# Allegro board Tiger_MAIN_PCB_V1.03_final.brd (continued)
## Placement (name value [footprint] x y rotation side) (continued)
R133  0  [RC0603N]  181.15 43.72 270 bottom
R134  20K  [RC0402N]  181.42 68.94 0 top
R136  33  [RC0402N]  178.14 37.99 90 top
R137  33  [RC0402N]  177.82 51.6 270 top
R138  33  [RC0402N]  176.02 37.98 90 top
R139  33  [RC0402N]  179.06 51.63 270 top
R140  2.2K  [RC0402N]  183.99 74.2 90 top
R142  0  [RC0402N]  172.97 54.66 0 bottom
R152  100k  [RC0402N]  238.32 43.35 270 bottom
R155  0  [RC0402N]  134.45 25.91 270 bottom
R168  0  [RC0402N]  229.78 96.46 0 bottom
R174  0  [RC0402N]  89.52 35.13 0 top
R175  0  [RC0402N]  76.05 56.64 270 top
R180  10K  [RC0402N]  80.56 56.19 0 top
R181  0  [RC0402N]  82.38 56.19 180 top
R182  1k  [RC0402N]  86.97 79.54 180 bottom
R183  0  [RC0402N]  160.35 92.37 0 top
R184  3.65K  [RC0402N]  229.01 98.95 180 bottom
R185  499  [RC0603N]  245.12 88.43 180 bottom
R187  0  [RC0402N]  89.49 40.08 180 top
R194  0  [RC0402N]  89.5 39.24 180 top
R196  100k  [RC0402N]  127.5 27.61 180 bottom
R197  0  [RC0402N]  88.96 44.49 270 top
R198  0  [RC0402N]  89.75 44.49 270 top
R199  10K  [RC0402N]  89.52 34.28 180 top
R200  0  [RC0402N]  78.07 56.19 0 top
R204  11K  [RC0402N]  229.78 97.24 0 bottom
R205  1.1k  [RC0402N]  229.78 98.06 180 bottom
R206  10K_NTC  [RC0402N]  231.61 98.06 180 bottom
R207  10K  [RC0402N]  233.15 93.7 0 bottom
R208  2k  [RC0402N]  235.46 83.25 180 top
R209  499  [RC0603N]  237.17 82.66 270 top
R210  1k  [RC0402N]  235.46 84.07 180 top
R211  3.01K  [RC0603N]  232.13 90.13 180 bottom
R212  365  [RC0402N]  233.15 92.75 0 bottom
R213  1.1k  [RC0402N]  242.98 101.36 180 bottom
R214  8.2K  [RC0402N]  242.98 100.41 0 bottom
R215  10K_NTC  [RC0402N]  244.29 100.88 90 bottom
R216  1k  [RC0402N]  242.35 94.65 270 bottom
R217  340  [RC0603N]  243.42 94.93 270 bottom
R218  0  [RC0402N]  231.77 83.43 90 bottom
R219  220K_NTC  [RC0603N]  231.24 87.34 270 bottom
R220  2.49k  [RC0402N]  237.39 96.34 270 bottom
R221  2k  [RC0402N]  245.2 81.64 0 bottom
R222  1.43K  [RC0603N]  238.42 99.13 270 bottom
R223  11K  [RC0402N]  245.51 84.06 90 bottom
R224  3.01K  [RC0603N]  243.4 91.66 270 bottom
R225  10K_NTC  [RC0402N]  245.01 80.41 0 bottom
R226  4.99K  [RC0402N]  240.24 98.66 270 bottom
R227  1k  [RC0402N]  239.46 98.66 270 bottom
R228  1k  [RC0402N]  243.73 81.19 90 bottom
R229  220K_NTC  [RC0603N]  236.36 98.64 270 bottom
R230  1.3K  [RC0402N]  245.51 95.96 270 bottom
R231  499  [RC0603N]  245.13 89.66 180 bottom
R232  12.1K  [RC0402N]  231.51 84.77 0 bottom
R233  100k  [RC0402N]  244.94 93.15 180 bottom
R234  88.7k  [RC0402N]  242.21 83.16 90 bottom
R235  64.9k  [RC0402N]  241.76 85.19 270 bottom
R236  0  [RC0402N]  44.22 57.03 180 bottom
R237  750  [RC0603N]  243.24 83.49 270 bottom
R238  0  [RC0402N]  230.96 83.43 90 bottom
R239  0  [RC0402N]  181.16 95.96 180 bottom
R240  0  [RC0402N]  89.52 36 0 top
R242  3.65K  [RC0402N]  242.98 102.2 0 bottom
R244  0  [RC0402N]  244.8 99.35 180 bottom
R246  0  [RC0805N]  123.74 80.68 180 bottom
R247  0  [RC0805N]  127.51 79.87 270 bottom
R249  0  [RC0402N]  211.74 96.83 0 bottom
R253  100k  [RC0402N]  183.73 51.09 90 top
R254  0  [RC0402N]  215.19 97.93 0 bottom
R255  0  [RC0402N]  181.47 60.26 0 top
R256  0  [RC0402N]  220.84 93.63 0 bottom
R258  0  [RC0402N]  162.33 89.4 90 bottom
R260  3.65K  [RC0402N]  245.2 82.45 0 bottom
R264  10K  [RC0402N]  179.63 60.26 180 top
R270  100K  [RC0402N]  175.67 29.56 180 bottom
R271  100K  [RC0402N]  175.76 28.62 0 bottom
R291  2.2  [RC0603N]  107.07 91.14 0 bottom
R303  2K  [RC1206N]  123.37 13.85 0 bottom
R306  0  [RC0402N]  112.55 46.72 90 bottom
R307  2.49k  [RC0603N]  120.62 34.37 90 bottom
R308  10k  [RC0402N]  132.91 41.55 180 bottom
R309  100k  [RC0402N]  115.81 44.28 0 bottom
R310  10k  [RC0402N]  132.91 42.69 180 bottom
R311  0  [RC0603N]  133.31 40 180 bottom
R312  0  [RC0603N]  133.32 38.79 0 bottom
R313  0  [RC0402N]  132.91 43.66 0 bottom
R315  1k  [RC0402N]  132.27 44.98 0 bottom
R316  15K  [RC0402N]  130.21 44.1 45 bottom
R317  0  [RC0603N]  132.57 46.23 0 bottom
R318  0  [RC0402N]  135.24 47.56 180 bottom
R319  0  [RC0603N]  101.6 31.91 0 top
R320  0  [RC0603N]  101.61 33.11 0 top
R321  10k  [RC0402N]  122.77 46.94 90 bottom
R322  0  [RC0603N]  101.47 34.95 0 top
R323  10k  [RC0402N]  123.58 46.94 90 bottom
R324  0  [RC0603N]  101.47 36.15 0 top
R325  1k  [RC0402N]  121.99 46.94 270 bottom
R326  1k  [RC0402N]  121.22 46.94 270 bottom
R327  0  [RC0603N]  104.62 37.84 0 bottom
R328  1k  [RC0402N]  127.65 35.48 90 bottom
R329  0  [RC0603N]  104.62 39.09 0 bottom
R330  0  [RC0603N]  104.59 40.83 0 bottom
R331  75  [RC0402N]  103.82 31.06 0 top
R332  75  [RC0402N]  103.74 34.03 0 top
R333  75  [RC0402N]  104.4 37.46 270 top
R334  75  [RC0402N]  104.4 39.49 90 top
R335  0  [RC0603N]  104.59 42.09 0 bottom
R336  0  [RC0603N]  9.59 89.64 90 top
R337  0  [RC0603N]  8.38 89.64 90 top
R338  0  [RC0603N]  5.26 89.92 90 top
R339  562  [RC0603N]  21.15 89.9 180 bottom
R340  0  [RC0603N]  6.47 89.92 90 top
R341  1k  [RC0402N]  22.99 90.18 270 bottom
R342  1k  [RC0402N]  25.27 88.5 180 bottom
R343  0  [RC0603N]  16.73 90.95 180 top
R344  0  [RC0603N]  16.73 92.15 180 top
R345  0  [RC0402N]  98.77 91 270 bottom
R346  1k  [RC0402N]  16.4 10.42 90 bottom
R347  0  [RC0603N]  35.06 20.09 180 bottom
R348  0  [RC0603N]  28.37 20.09 180 bottom
R349  75  [RC0402N]  8.88 19.5 0 bottom
R350  75  [RC0402N]  8.89 18.68 0 bottom
R355  4.7K  [RC0402N]  13.41 11.29 90 bottom
R356  4.7K  [RC0402N]  10.99 11.28 90 bottom
R357  20K  [RC0402N]  16.71 13.99 270 bottom
R358  39.2K  [RC0402N]  18.29 13.86 90 bottom
R359  20K  [RC0402N]  17.5 13.86 90 bottom
R360  0  [RC0603N]  20.9 15.87 0 bottom
R361  0  [RC0603N]  20.91 17.1 0 bottom
R362  33  [RC0402N]  19.62 18.18 0 bottom
R363  1k  [RC0402N]  23.68 25.09 180 top
R364  1k  [RC0402N]  25.23 27.18 90 top
R365  0  [RC0603N]  25.23 24.88 270 top
R366  0  [RC0603N]  26.22 27.65 270 top
R368  1.8K  [RC0603N]  192.67 12.77 0 bottom
R369  10k  [RC0402N]  19.22 29.05 0 bottom
R370  10k  [RC0402N]  20.66 26.25 90 bottom
R371  10k  [RC0402N]  24.09 29.87 270 bottom
R372  0  [RC0402N]  20.65 28.3 270 bottom
R373  1K  [RC0402N]  22.45 29.43 180 bottom
R377  0  [RC0402N]  136.94 38.75 0 bottom
R378  100k  [RC0402N]  135.38 34.66 90 bottom
R379  10K  [RC0402N]  44.19 69.43 0 bottom
R380  10K  [RC0402N]  44.19 70.71 0 bottom
R381  0  [RC0402N]  63.19 70.32 270 bottom
R382  10K  [RC0402N]  183.98 58.59 180 top
R383  0  [RC0805N]  36.8 56.84 90 bottom
R384  10K  [RC0402N]  55.14 74.22 270 bottom
R385  240  [RC0402L]  206.37 14.27 90 bottom
R386  10K  [RC0402N]  196.12 13.69 270 bottom
R387  10K  [RC0402N]  56.24 74.22 270 bottom
R388  10K  [RC0402N]  52.78 74.21 270 bottom
R389  10K  [RC0402N]  171.11 10.87 270 top
R390  0  [RC0402N]  64.52 69.86 180 bottom
R391  2.2  [RC0603N]  160.18 42.21 180 top
R392  220K  [RC0402N]  165.58 42.02 270 top
R393  10K  [RC0402N]  53.55 74.21 270 bottom
R395  0  [RC0402N]  44.53 64.85 180 bottom
R396  0  [RC0402N]  54.36 74.21 270 bottom
R397  0  [RC0402N]  57.04 74.21 270 bottom
R398  0  [RC0603N]  66.65 65.97 0 bottom
R399  10K  [RC0402N]  44.22 65.78 0 bottom
R400  10K  [RC0402N]  44.22 67.36 0 bottom
R401  100  [RC0402N]  63.62 62.02 0 bottom
R402  0  [RC0402N]  59.61 74.18 270 bottom
R403  0  [RC0402N]  70.27 61.98 180 bottom
R404  10K  [RC0402N]  44.22 66.56 0 bottom
R405  10K  [RC0402N]  44.22 58.74 0 bottom
R406  100k  [RC0402N]  42.93 58.27 90 bottom
R407  10K  [RC0402N]  42.3 61.9 90 bottom
R408  100k  [RC0402N]  61.44 63.94 270 top
R409  0  [RC0402N]  44.22 68.29 180 bottom
R410  0  [RC0402N]  63.58 61.25 180 bottom
R412  0  [RC0402N]  70.28 61.14 180 bottom
R413  100  [RC0402N]  58.33 74.21 90 bottom
R414  10K  [RC0402N]  63.59 60.47 0 bottom
R415  100k  [RC0402N]  65.73 58.12 0 bottom
R416  0  [RC0402N]  65.49 62.68 0 bottom
R417  0  [RC0402N]  51.22 74.26 90 bottom
R419  1k  [RC0402N]  44.22 57.88 180 bottom
R420  10K  [RC0402N]  46.3 74.25 270 bottom
R421  10K  [RC0402N]  47.15 74.25 90 bottom
R422  10K  [RC0402N]  50.45 74.25 270 bottom
R423  10K  [RC0402N]  49.62 74.25 90 bottom
R424  0  [RC0402N]  61.52 74.48 270 bottom
R425  10M  [RC0402N]  62.29 73.53 90 bottom
R426  100k  [RC0402N]  44.22 62.41 0 bottom
R427  4.7K  [RC0402N]  46.53 62.13 180 top
R428  4.7K  [RC0402N]  59.87 63.39 0 top
R429  0  [RC0402N]  128.75 82.38 180 bottom
R434  0  [RC0402N]  54.74 76.85 90 bottom
R435  10K  [RC0402N]  195.28 14.64 90 bottom
R436  10K  [RC0402N]  171.98 10.87 270 top
R437  0  [RC0402N]  55.57 76.85 90 bottom
R440  100k  [RC0402N]  130.39 85.71 270 bottom
R452  0  [RC0402N]  131.08 82.8 90 top
R453  0  [RC0402N]  130.26 81.73 270 top
R454  0  [RC0402N]  135.51 81.49 270 top
R455  10k  [RC0402N]  135.52 83.27 90 top
R456  10k  [RC0402N]  130.26 83.52 90 top
R457  0  [RC0402N]  70.29 60.31 0 bottom
R458  0  [RC0402N]  48.81 74.26 90 bottom
R462  0  [RC0402N]  47.99 74.26 90 bottom
R463  1M  [RC0402N]  27.39 62.4 180 bottom
R464  34K  [RC0402N]  185.55 29.26 0 bottom
R466  0  [RC0402N]  63.89 58.12 0 bottom
R468  0 ohm  [RC0805N]  170.97 24.34 180 bottom
R469  16k  [RC0603N]  185.57 28.21 180 bottom
R470  0  [RC0402N]  175.67 30.36 180 bottom
R471  240  [RC0402L]  215.15 21.79 90 bottom
R472  240  [RC0402L]  215.98 21.79 90 bottom
R476  0  [RC0402N]  194.43 12.48 90 bottom
R487  0  [RC0402N]  66.56 70.28 0 bottom
R488  0  [RC0402N]  64.59 63.95 180 bottom
R489  10K  [RC0402N]  169.44 10.87 270 top
R490  240  [RC0402L]  216.91 15.01 90 bottom
R491  10K  [RC0402N]  170.25 10.87 270 top
R492  240  [RC0402L]  216.81 21.78 270 bottom
R493  240  [RC0402L]  214.25 21.79 270 bottom
R494  240  [RC0402L]  213.35 21.79 270 bottom
R495  240  [RC0402L]  216.87 17.26 270 bottom
R496  240  [RC0402L]  217.85 21.77 270 bottom
R497  240  [RC0402L]  215.31 15.8 270 bottom
R498  470  [RC0402N]  213.85 14.28 270 bottom
R501  240  [RC0402L]  212.44 17.36 270 bottom
R502  0  [RC0402N]  213.84 16.08 270 bottom
R506  10K  [RC0402N]  56.86 75.97 180 bottom
R512  2  [RC0402N]  229.63 49.79 270 top
R513  25  [RC0402N]  228.07 49.79 270 top
R521  0  [RC0402N]  242.97 71.08 270 top
R522  0  [RC0402N]  243.92 71.08 270 top
R523  4.7K  [RC0402N]  245.61 76.19 90 top
R524  4.7K  [RC0402N]  245.61 74.35 90 top
R528  0  [RC0402N]  128.86 88.79 0 top
R534  16k  [RC0603N]  145.71 48.53 0 top
R535  100K  [RC0402N]  141.83 55.72 180 top
R536  18k  [RC0402N]  143.43 48.53 0 top
R537  100K  [RC0402N]  144.3 57.43 0 top
R541  0  [RC0402N]  129.42 82.4 90 top
R543  12k  [RC0603N]  242.35 37.71 0 bottom
R544  100k  [RC0402N]  241.93 41.56 90 bottom
R545  0  [RC0402N]  242.75 41.56 90 bottom
R546  12K  [RC0402N]  235.46 43.94 180 bottom
R547  20K  [RC0402N]  235.46 43.16 180 bottom
R548  0  [RC0402N]  239.11 41.54 90 bottom
R549  0  [RC0402N]  238.33 41.54 90 bottom
R550  0  [RC0402N]  236.76 41.53 90 bottom
R551  0  [RC0402N]  237.54 41.54 90 bottom
R552  0  [RC0402N]  239.88 41.55 270 bottom
R553  560K  [RC0603N]  240.88 42.01 270 bottom
R554  0  [RC0402N]  48.04 58.16 0 top
R555  100k  [RC0402N]  49.83 58.16 0 top
R557  1k  [RC0603N]  59.04 18.67 180 top
R558  1k  [RC0402N]  59.75 12.18 180 top
R559  1.8k  [RC0603N]  46.17 91.19 270 bottom
R560  1k  [RC0603N]  48.72 92.7 270 bottom
R561  1k  [RC0402N]  51.51 90.03 90 bottom
R562  1k  [RC0603N]  42.53 23.47 0 top
R563  1k  [RC0402N]  40.57 22.45 180 top
R564  0  [RC0603N]  46.95 21.16 0 top
R565  0  [RC0603N]  46.95 19.89 0 top
R567  0  [RC0603N]  62.54 21.2 0 top
R568  0  [RC0603N]  62.54 19.93 0 top
R569  30k  [RC0603N]  42.82 24.8 0 top
R570  30k  [RC0603N]  59.04 17.44 0 top
R590  10  [RC0603N]  239.22 82.57 180 top
R591  10  [RC0603N]  233.95 85.88 90 top
R606  0  [RC0402N]  128.45 83.96 0 top
R607  10K  [RC0402N]  160.22 18.71 270 top
R608  10K  [RC0402N]  161.88 13.56 0 top
R609  100  [RC0402N]  161.88 14.41 0 top
R611  100  [RC0402N]  100.78 11.32 0 top
R613  0 ohm  [RC0805N]  19.05 61.13 0 top
R616  0  [RC0402N]  181.33 51.09 270 top
R620  33  [RC0402N]  188.96 41.54 90 top
R621  33  [RC0402N]  196.23 48.9 90 top
R623  33  [RC0402N]  197.83 48.9 90 top
R624  0  [RC0402N]  192.7 44.4 315 top
R625  10k  [RC0402N]  191.29 41.61 270 top
R626  33  [RC0402N]  193.18 41.62 90 top
R627  0 ohm  [RC0603N]  244.57 20.51 90 top
R628  0 ohm  [RC0603N]  245.84 20.5 90 top
R629  0 ohm  [RC0603N]  7.89 12.75 180 top
R630  0 ohm  [RC0603N]  7.9 11.53 180 top
R632  150k  [RC0402N]  176.69 66.12 0 top
R633  1k  [RC0402N]  183.65 77.36 0 top
R636  18.7K  [RC0603N]  124.44 78.1 90 top
R638  12K  [RC0603N]  121.23 81.03 90 top
R645  430k  [RC0603N]  104.87 96.9 0 bottom
R648  430k  [RC0603N]  116.95 85.29 180 top
R660  0  [RC0402N]  166.28 55.3 90 top
R662  0  [RC0402N]  169.9 53.28 180 top
R663  100K  [RC0402N]  167.99 53.28 180 top
R667  0  [RC0402N]  235.46 80.92 180 top
R668  0  [RC0402N]  238.96 81.57 180 top
R669  88.7k  [RC0402N]  232.82 86.55 180 bottom
R671  7.5K  [RC0402N]  232.81 88.12 180 bottom
R672  100  [RC0603N]  247.04 97.51 0 bottom
R673  100  [RC0603N]  243.48 86.45 90 bottom
R674  0  [RC0402N]  245.26 97.79 270 bottom
R675  0  [RC0402N]  248.43 95.98 270 bottom
R678  7.5K  [RC0402N]  236.36 96.34 270 bottom
R680  100k  [RC0402N]  236.89 94.14 270 bottom
R681  10  [RC0603N]  240.17 101.93 0 bottom
R682  10  [RC0603N]  240.25 95.98 180 bottom
R683  0  [RC0402N]  239.9 102.94 0 bottom
R684  0  [RC0402N]  239.97 97.04 0 bottom
R685  0  [RC0402N]  233.37 84.97 180 bottom
R686  10  [RC0603N]  237.42 82.37 90 bottom
R689  0  [RC0402N]  182.27 100.71 90 bottom
R690  0  [RC0402N]  187.24 94.17 0 bottom
R707  3.3k  [RC0402N]  175.73 51.09 0 top
R708  3.3k  [RC0402N]  174.75 37.99 90 top
R709  3.3k  [RC0402N]  177.27 37.99 90 top
R711  33  [RC0402N]  175.73 51.88 0 top
R713  100  [RC0402N]  235.65 81.96 180 bottom
R714  49.9  [RC0402N]  233.79 81.96 180 bottom
R715  49.9  [RC0402N]  233.32 83.29 270 bottom
R716  100k  [RC0402N]  231.03 82.65 90 top
R717  1k  [RC0201N]  230.18 79 180 top
R718  0  [RC0402N]  182.13 51.09 90 top
R719  1.5k  [RC0402N]  178.33 81.37 0 top
R720  0  [RC0402N]  228.57 52.63 180 bottom
R721  1k  [RC0402N]  229.99 75.98 0 top
R722  1k  [RC0201N]  230.18 78.33 180 top
R723  1k  [RC0201N]  230.52 79.9 0 top
R724  1k  [RC0201N]  231.56 78.34 0 top
R725  1k  [RC0201N]  230.18 75.08 180 top
R726  1k  [RC0201N]  231.57 77.06 180 top
R727  1k  [RC0201N]  231.56 77.73 0 top
R728  1k  [RC0201N]  230.19 74.25 180 top
R729  1k  [RC0201N]  231.57 76.46 0 top
R730  1k  [RC0201N]  231.57 74.25 0 top
R731  1k  [RC0201N]  231.57 75.84 0 top
R732  10K  [RC0402N]  177.51 66.94 180 top
R733  10K  [RC0402N]  183.99 59.38 180 top
R748  1  [RC0603N]  100.35 55.95 90 bottom
R754  16k  [RC0603N]  116.95 86.52 180 top
R755  10.9k  [RC0603N]  127.48 78.1 270 top
R756  10k  [RC0603N]  126.16 78.1 90 top
R762  10k  [RC0603N]  159.36 45.53 180 top
R763  300  [RC0603N]  167.61 44.28 0 top
R764  10k  [RC0603N]  167.64 47.71 0 top
R765  0  [RC0603N]  158.93 53.97 90 top
R766  30k  [RC0603N]  167.64 46.48 180 top
R767  100k  [RC0402N]  165.37 48.34 0 top
R768  0  [RC0603N]  162.25 48.61 0 top
R769  100k  [RC0402N]  163.94 42.02 270 top
R770  0  [RC0402N]  155.08 46.52 270 bottom
R771  20k  [RC0603N]  157.92 48.1 0 bottom
R772  100K  [RC0402N]  157.47 50.15 180 bottom
R773  10k  [RC0603N]  157.93 46.83 180 bottom
R774  100K  [RC0402N]  157.48 50.96 180 bottom
R775  10K  [RC0402N]  13.04 69.6 0 bottom
R776  13k ohm  [RC0603N]  14.69 67.49 270 bottom
R778  51k  [RC0603N]  21.12 67.37 90 bottom
R779  51k  [RC0603N]  13.14 67.61 270 bottom
R780  10K  [RC0402N]  18.81 70.07 0 bottom
R781  0  [RC0603N]  13.07 80.71 180 bottom
R782  30k  [RC0603N]  19.91 67.49 90 bottom
R783  2.2  [RC0603N]  15.31 77.62 270 top
R784  20K  [RC0603N]  18.7 67.49 270 bottom
R785  20K  [RC0603N]  15.89 67.49 270 bottom
R786  0  [RC0603N]  20.79 84.77 180 top
R787  2.2  [RC0603N]  26.01 78.54 90 top
R788  390K  [RC0603N]  143.14 14.03 270 bottom
R789  100K  [RC0402N]  152.59 14.94 90 bottom
R791  1M  [RC0402N]  144.74 13.34 180 bottom
R792  10k  [RC0603N]  143.12 16.77 90 bottom
R793  0  [RC2512N]  144.17 21.24 0 bottom
R794  100  [RC1206N]  153.17 18.86 90 bottom
R795  1k  [RC0402N]  196.59 41 270 top
R796  1k  [RC0402N]  195.64 41.05 90 top
R799  1k  [RC0402N]  189.77 41.54 90 top
R800  0  [RC0603N]  152.45 44.79 180 bottom
R801  0  [RC0603N]  149.48 57.66 0 top
R802  100k  [RC0402N]  73.63 101.61 0 bottom
R806  100k  [RC0402N]  25.16 60.77 270 bottom
R807  1k  [RC0402N]  28.56 78.83 90 top
R808  1k  [RC0402N]  28.73 66.67 180 bottom
R809  100k  [RC0402N]  25.61 62.4 0 bottom
R810  1k  [RC0402N]  29.33 61.1 90 top
R811  68  [RC0402N]  236.5 49.6 270 bottom
R812  1M  [RC0402N]  238.09 49.6 90 bottom
R813  100K  [RC0402N]  237.32 49.6 270 bottom
R814  100K  [RC0402N]  29.79 72.71 0 bottom
R815  47  [RC0603N]  183.56 86.08 0 top
R816  470  [RC0402N]  159.71 69.72 0 top
R817  100  [RC0603N]  37.42 75 180 top
R818  100  [RC0603N]  35.93 61.29 270 top
R819  221  [RC0402N]  147.94 48.26 90 top
R820  22  [RC0402N]  232.13 42.77 0 bottom
R821  1M  [RC0402N]  27.96 72.71 0 bottom
R825  0  [RC0402N]  156.08 45.18 0 bottom
R826  0  [RC0603N]  184.44 39.36 180 bottom
R827  0  [RC0402N]  170.55 80.61 0 top
R828  0  [RC0402N]  170.54 81.4 0 top
R829  10K  [RC0402N]  45.89 70.49 0 top
R830  100k  [RC0402N]  47.69 65.77 0 top
R831  0  [RC0603N]  20.91 14.63 0 bottom
R883  39K  [RC0603N]  107.63 96.9 180 bottom
R958  100k  [RC0402N]  120.76 83.06 180 top
R2978  0  [RC0603N]  40.81 89.2 180 top
R2979  0  [RC0603N]  40.81 90.43 180 top
R2980  0  [RC0603N]  35.21 89.91 90 top
R2981  0  [RC0603N]  36.51 89.91 90 top
R2982  0  [RC0603N]  33.52 89.65 90 top
R2983  0  [RC0603N]  32.24 89.65 90 top
R2984  0  [RC0402N]  140.97 78.57 270 bottom
R2985  0  [RC0402N]  138.86 90.47 0 top
R2986  4.99K  [RC0402N]  137.65 78.75 90 bottom
R2987  4.99K  [RC0402N]  136.88 78.75 90 bottom
R2988  4.7K  [RC0402N]  130.46 78.72 180 top
R2989  10K  [RC0402N]  148.78 81.72 0 bottom
R2990  10K  [RC0402N]  148.78 80.71 0 bottom
R2991  4.7K  [RC0402N]  137.54 76.27 0 top
R2992  4.7K  [RC0402N]  139.34 76.27 180 top
R2993  4.7K  [RC0402N]  139.22 78.75 270 bottom
R2994  4.7K  [RC0402N]  139.98 78.75 90 bottom
R2995  4.7K  [RC0402N]  137.69 84.31 90 top
R2996  4.7K  [RC0402N]  139.96 77.02 180 bottom
R2997  0  [RC0402N]  138.86 89.67 0 top
R2998  2k  [RC0402N]  132.31 78.72 180 top
R2999  2k  [RC0402N]  134.08 78.72 0 top
R3000  0  [RC0402N]  134.97 28.15 0 bottom
R3001  0  [RC0402N]  134.97 28.95 0 bottom
R3004  0  [RC0402N]  131.72 25.43 0 bottom
R3005  0  [RC0402N]  135 27.3 0 bottom
R3007  0  [RC0402N]  129.3 27.61 180 bottom
R3008  1k  [RC0402N]  73.63 102.43 0 bottom
R3009  10K  [RC0402N]  72.32 101.29 90 bottom
R3089  0  [RC0402N]  117.28 89.44 180 top
R3090  0  [RC0402N]  116.82 88.13 90 top
R3091  0  [RC0402N]  124.45 83.13 0 top
R3093  100  [RC0402N]  129.24 88 0 top
R3094  0  [RC0402N]  126.76 83.13 180 top
R3095  0  [RC0402N]  87.83 92.36 180 bottom
R3096  1M  [RC0402N]  104.87 96.9 0 bottom
R3097  0  [RC0402N]  87.36 91.04 90 bottom
R3098  0  [RC0603N]  122.69 81.03 90 top
R3099  0  [RC0603N]  124.44 81.03 90 top
R3100  0  [RC0603N]  126.16 81.03 90 top
R3101  0  [RC0603N]  127.48 81.03 90 top
R3102  20K  [RC0402N]  122.68 78.51 90 top
R3106  1M  [RC0402N]  125.82 89.79 180 top
R3107  10k  [RC0402N]  131.02 89.56 180 top
R3108  100k  [RC0402N]  132.55 85.33 0 top
R3109  0  [RC0402N]  128.86 90.36 180 top
R3110  0  [RC0402N]  128.87 89.57 0 top
R3111  1M  [RC0402N]  136.87 89.07 0 top
R3112  100k  [RC0402N]  128.78 86.71 270 top
R3113  27K  [RC0402N]  107.63 96.9 0 bottom
R3114  51m  [RC0805N]  100.34 89.18 0 bottom
R3115  51m  [RC0805N]  100.34 87.39 0 bottom
R3116  51m  [RC0805N]  100.34 85.56 0 bottom
R3117  51m  [RC0805N]  100.34 83.75 0 bottom
R3118  0  [RC0402N]  88.31 91.04 90 bottom
R3119  4.7K  [RC0402N]  15.07 11.69 0 bottom
R3120  1k  [RC0402N]  11.77 11.27 270 bottom
R3121  1k  [RC0402N]  12.63 11.29 270 bottom
R3122  0  [RC0402N]  52.01 74.22 270 bottom
R3123  0  [RC0402N]  135.07 89.07 0 top
R3124  0  [RC0402N]  216.21 49.7 270 top
R3125  0  [RC0402N]  217 49.7 270 top
R3126  0  [RC0402N]  121.38 28.68 0 top
R3127  0  [RC0402N]  121.38 27.88 0 top
R3128  0  [RC0402N]  74.8 56.65 270 top
R3129  2.2  [RC0805N]  115.97 27.38 0 top
R3130  0  [RC0402N]  85.32 93.89 270 bottom
R3131  0  [RC0402N]  86.38 93.89 270 bottom
R3132  0  [RC0402N]  88.33 93.89 270 bottom
R3133  0  [RC0402N]  87.39 93.89 270 bottom
SW1  THBM02  [TH-SW-420P-2N]  122.32 8.39 0 top
TP2  TP  [TEST100]  173.77 55.82 180 bottom
TP3  TP  [TEST60]  182.03 52.54 0 bottom
TP4  TP  [TEST60]  176.04 50.49 0 bottom
TP5  TP  [TEST60]  230.1 77.52 0 top
TP6  TP  [TEST60]  191.85 48.78 180 top
TP7  TP  [TEST100]  172.5 56 180 bottom
TP8  TP  [TEST60]  192.64 50.09 180 top
TP10  TP  [TEST60]  191.49 51.17 180 top
TP11  TP  [TEST60]  192.99 48.98 180 top
TP12  TP  [TEST60]  183.14 53.99 180 top
TP13  TP  [TEST60]  193.07 61.51 0 bottom
TP14  TP  [TEST60]  193.03 47.94 0 top
TP16  TP  [TEST60]  176.86 51.18 180 bottom
TP17  TP  [TEST60]  228.63 81.16 180 bottom
TP18  TP  [TEST60]  226.57 82.52 0 top
TP20  TP  [TEST60]  227.47 82.99 0 top
TP21  TP  [TEST60]  227.23 81.04 180 bottom
TP22  TP  [TEST60]  220.41 85.63 0 top
TP23  TP  [TEST60]  220.41 84.63 0 top
TP25  TP  [TEST60]  217.62 82.24 0 top
TP35  TP  [TEST60]  204.73 71.83 180 bottom
TP36  TP  [TEST60]  204.72 62.81 180 bottom
TP37  TP  [TEST60]  220.16 63.44 180 bottom
TP38  TP  [TEST60]  220.12 62.61 180 bottom
TP39  TP  [TEST60]  200.57 60.87 180 bottom
TP40  TP  [TEST60]  200.15 61.81 180 bottom
TP43  TP  [TEST60]  185.03 53.25 0 top
TP44  TP  [TEST60]  181.46 69.85 0 top
TP45  TP  [TEST60]  181.43 70.88 0 top
U1  SKL_ULT  [SKL_42X24_P65_1356_KOZ]  206.84 66.14 180 top
U2  SN74LVC1G08DCKR  [SOT65P190-5N]  168.09 50.94 270 top
U4  SN74LVC1G07DCK  [SOT65P210-5N]  240.53 44.7 180 bottom
U5  EMC1402  [TSOP65P490-8N]  243.48 76.07 90 top
U6  SN74LVC1G08DCKR  [SOT65P190-5N]  168.47 54.95 180 top
U8  APL3512A/B  [SOT95P280-5N]  115.03 46.41 180 bottom
U9  RTL8105E/8111E  [QFN40P600X600-48N]  125.8 40.5 0 bottom
U10  SN74LVC1G08DCKR  [SOT65P190-5N]  135.61 45.34 270 bottom
U11  EG24A005S  [SOP99P996-24N]  110.45 36.53 180 top
U12  TPS2065  [SOT95P280-5N]  22.24 87.53 0 bottom
U13  TPD2EUSB30DRTR  [SOP35P100-3N]  5.9 91.97 0 top
U14  TPD2EUSB30DRTR  [SOP35P100-3N]  14.52 91.5 90 top
U16  ALC282  [QFN40P600X600-48AN]  14.53 18.96 180 bottom
U17  5_SN74LVC1G08DCKR  [SOT65P190-5N]  18.36 27.35 180 bottom
U18  SN74LVC1G08DCKR  [SOT65P190-5N]  137.41 26.25 90 bottom
U19  APL3512A/B  [SOT95P280-5N]  137.43 35.44 90 bottom
U21  APL5930  [SOP127P600-9N]  180.42 27.57 180 bottom
U22  IT8587E/DX  [LQFP40P1600X1600-128N]  54.12 64.06 180 bottom
U23  SN74LVC1G06DCK  [SOT65P210-5N]  40.14 61.74 180 bottom
U24  EN25F16-100HIP  [SOIC127P800-8N]  53.38 62.75 180 top
U25  APL3512A/B  [SOT95P280-5N]  128.28 84.89 270 bottom
U27  SN74LVC1G08DCKR  [SOT65P190-5N]  133.29 82.8 180 top
U29  APW8861QBI-TRG  [QFN40P400X400-35N]  237.95 36.77 0 bottom
U35  APL5930  [SOP127P600-9N]  145.6 53.18 90 top
U38  TPS2065  [SOT95P280-5N]  48.95 89.56 0 bottom
U39  TPS2065  [SOT95P280-5N]  41.8 20.36 180 top
U40  TPS2065  [SOT95P280-5N]  60.23 14.68 270 top
U41  APW7141  [PQFP50P365X365-14N]  163.28 45.38 90 top
U42  W25Q64FV  [SOIC127P540-8N]  175.26 41.48 90 top
U45  ISL95808  [DFN50P200X200-8N]  178.5 95.72 180 bottom
U50  ISL95808  [DFN50P200X200-8N]  209.51 96.57 180 bottom
U54  ISL95808  [DFN50P200X200-8N]  160.5 88.49 180 bottom
U56  APL3526  [SON50P200X200-8N]  172.95 81.45 0 top
U59  APL3526  [SON50P200X200-8N]  158.01 60.73 0 bottom
U67  APL3526  [SON50P200X200-8N]  169.16 60.6 270 top
U70  APW8804QB  [TDFN50P300X300-10N]  154.55 49.42 270 bottom
U71  TPS51275/C  [QFN40P300X300-20N]  15.96 71.34 90 bottom
U95  GL834L  [QFN50P400X400-24BN]  74.02 97.16 180 bottom
U103  ISL95857  [TQFN40P500X500-40N]  237.97 88.92 0 bottom
U2523  TPD2EUSB30DRTR  [SOP35P100-3N]  32.81 91.73 0 top
U2524  TPD2EUSB30DRTR  [SOP35P100-3N]  38.71 89.83 90 top
U2525  AT24C02A  [SOIC127P600-8N]  137.51 72.06 90 top
U2526  PS8625QFN56G  [QFN40P700X700-56AN]  140.35 84.21 180 bottom
U2527  AT24C02A  [SOIC127P600-8N]  131.9 74.57 90 top
U2529  APW7228BRI-TRG  [TSSOP65P640-16AN]  123.28 86.37 0 top
X1  X3S024000FK1H  [OSC170P320X250-4N]  207.08 84.98 0 top
X2  32.768KHZ  [SMY126X63]  188.27 43.35 90 bottom
X3  X3S025000FK1H  [OSC170P320X250-4N]  123.77 30.72 180 bottom
X4  32.768KHz  [OSC120P150X670-4L]  69.18 73.55 270 bottom
X5  Q13MC1461000200SM26BSPRC  [OSC127P200X600-2L]  70.14 73.55 270 bottom

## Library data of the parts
B1 = MIC-2_0
C1 C32 C72 C75 C135 C234-C237 = C: signal model: DEFAULT_CAPACITOR_10000pF_2_1
C2 C5-C8 C13 C15 C16 C18 C22-C31 C33 C34 C36-C42 C44-C60 C66-C69 C71 C73 C74 C76-C129 C138-C144 C150-C185 C188-C230 C238-C245 C248 C250 C274 C281-C287 C293-C297 C301-C306 C308-C334 C338-C341 C343 C344 C371-C374 C377-C381 C384 C386-C393 C397-C400 C403 C406 C409 C410 C413 C414 C417-C419 C421 C422 C424 C426 C431-C436 C439-C459 C464 C470 C477 C479-C488 C490 C491 C495 C510-C513 C523 C535 C563-C566 C608-C610 C633-C635 C640-C646 C648-C665 C671 C673 C678-C680 C685-C690 C694 C695 C698-C702 C704-C742 C746 C747 C758 C759 C761 C767 C770-C772 C776 C778-C782 C790-C797 C802-C808 C942 C2762-C2768 C2770-C2788 C2790 C2833 C2836-C2838 C2844-C2850 C2852-C2854 = C
C3 C4 C249 C264 C299 C307 C368 C369 C376 C382 C396 C402 C404 C416 C425 C427-C430 C461 C463 C469 C489 C607 C669 C693 C696 C697 C703 C768 C773-C775 C777 C784-C787 C992 C2769 C2834 C2839 = C: alternate symbols: (T:CC0603N;B:CC0603M)
C9-C12 C411 C412 = C: signal model: C_CC0402N_100NF_100nF
C14 C298 C603 C2835 = C: alternate symbols: (T:CC1210N;B:CC1210M)
C17 C21 C70 C146 C149 = C: signal model: DEFAULT_CAPACITOR_1e+06pF_2_1
C19 = C: signal model: DEFAULT_CAPACITOR_2200pF_2_1
C20 = C: signal model: DEFAULT_CAPACITOR_470.000000pF_2_1
C35 C133 C137 C232 C233 = C: signal model: DEFAULT_CAPACITOR_1e+07pF_2_1
C43 C130 C131 C134 C136 C145 C148 C231 C300 = C: signal model: DEFAULT_CAPACITOR_100000pF_2_1
C61-C65 = C: signal model: DEFAULT_CAPACITOR_4.7e+07pF_2_1
C132 C147 = C: signal model: DEFAULT_CAPACITOR_1000pF_2_1
C186 C187 = C: signal model: DEFAULT_CAPACITOR_20.000000pF_2_1
C292 C2840-C2843 = C: signal model: C_CC0402N_0.01UF_0.01uF
C375 C2789 = C: alternate symbols: (T:CC0805N;B:CC0805M)
C383 C385 C401 C405 C407 C408 C2791 = C: alternate symbols: (T:CC1206N;B:CC1206M)
C394 C395 = C: signal model: C_CC0402N_0.1U_0.1u
CN1 = CN-DDR4-260+2
CN3 = CN-SATA-7+15+2-S
CN5 = CN75+2-J8
CN7 = BAT_CON_2
CN9 = CN-JACK-3
CN10 = RJ45_8+2
CN14 CN21 CN42 = CN2+2-S
CN16 = CN20+2-S
CN22 CN23 = CN-USB-4+2
CN24 CN36 = CN-USB-9+4
CN25 = CN4+2-S
CN26 = CN75+2-S1_1
CN35 = CN40d+2_1
CN37 = SD_11+4
CN41 = CN2-S
CP1-CP4 = C_P: signal model: DEFAULT_CAPACITOR_2.2e+08pF_2_1
CP7 CP9 CP13 CP20 = C_P: alternate symbols: (T:CCP7343N;B:CCP7343M)
CP8 CP10 CP14 CP15 CP18 CP50-CP52 = C_P
D1 D6-D8 D19-D23 D26 D28 D30 D31 D38 D42 D2512 D2513 = D
D17 D18 D29 = D: alternate symbols: (T:sod2514n;B:SOD2514M)
D24 D25 = D_2PN: alternate symbols: (T:SOT95P280-3N;B:SOT95P280-3M)
F2-F5 F8 F9 = FUSE
FB2 FB3 FB7-FB9 FB12-FB14 FB19 FB20 FB22-FB26 FB40 = FB
FB4 FB5 FB15 = FB: alternate symbols: (T:FB1206N;B:FB1206M)
FB6 FB16-FB18 FB37-FB39 FB44 FB45 = FB: alternate symbols: (T:FB0603N;B:FB0603M)
FB10 FB11 = FB: signal model: DEFAULT_RESISTOR_120.000000OHM_2_1
FB21 = FB: alternate symbols: (T:FB0603N;B:FB0603M); signal model: DEFAULT_RESISTOR_120.000000OHM_2_1
FIL1-FIL7 FIL9 FIL10 FIL14-FIL16 = FIL4_DXW21BN7511TB
J2 J3 = CN-EARPHONE-5_15
J5 = CN6+2-S
L3-L5 L9 L12 L25 L26 L32 LPM1 LPM8 LPM10 = L
LED2 = LED
MARK1-MARK8 = MARK
MH1 MH4 MH6-MH10 MH22 MH26-MH33 = H
Q1 Q19 Q48 Q74 = NMOS-GSD_0
Q2 Q3 Q20 Q76 = NMOS-GSD
Q4 Q36 Q45 Q46 Q51-Q53 Q56 Q57 Q61-Q67 = NMOS-GSD: alternate symbols: (T:SOT95P240-3N;B:SOT95P240-3M)
Q21 Q59 = NMOS-GSD: alternate symbols: (T:SOT95P280-3N;B:SOT95P280-3M)
Q26 = NPN-BEC: alternate symbols: (T:SOT95P230-3N;B:SOT95P230-3M)
Q30 Q31 Q55 Q73 = SI4814: alternate symbols: (T:SOIC127P600-8N;B:SOIC127P600-8M)
Q43 Q60 Q68-Q72 = PWR_N_MOSFET
Q47 Q49 = NPN-BEC+2R: alternate symbols: (T:SOT65P210-3N;B:SOT65P210-3M)
Q58 = PWR_P_MOSFET: alternate symbols: (T:SOIC127P600-8N;B:SOIC127P600-8M)
Q95 = 3_APM1110NU
R1 R67 = R: signal model: DEFAULT_RESISTOR_100000OHM_2_1
R2 R4-R10 R13 R15-R19 R21-R26 R29-R44 R50-R55 R57-R62 R69 R71 R72 R74 R80-R86 R90 R92-R95 R97-R99 R102 R104 R105 R112-R122 R124-R128 R131-R133 R140 R142 R152 R168 R180 R183-R185 R196 R199 R204-R216 R218 R220 R221 R223-R228 R230 R231 R233-R236 R238 R239 R242 R244 R249 R253-R256 R258 R260 R264 R309 R315 R345 R347-R350 R355-R358 R362-R366 R378-R382 R384-R390 R392 R395 R396 R399-R410 R412-R417 R419 R421-R426 R434-R437 R440 R457 R458 R462 R464 R466 R468-R472 R476 R487-R498 R501 R502 R506 R521-R524 R534 R536 R541 R544-R552 R554 R555 R558 R559 R561 R563 R590 R591 R606-R609 R611 R613 R616 R624 R627-R630 R632 R645 R648 R660 R662 R667-R669 R671 R674 R675 R678 R680-R686 R689 R690 R707-R709 R713-R720 R722-R733 R754-R756 R762 R767 R769 R770 R775 R776 R778-R780 R792-R796 R799-R802 R811 R815 R819 R820 R825-R830 R883 R2978-R2983 R2986-R2996 R2998-R3001 R3004 R3005 R3007-R3009 R3089-R3091 R3093-R3095 R3097-R3102 R3106 R3109 R3111 R3113 R3118-R3122 R3124-R3127 R3130-R3133 = R
R3 R11 R12 R14 R27 R28 R70 R75 R91 R106-R111 R123 R182 R217 R219 R222 R229 R237 R291 R311 R312 R317 R325 R326 R328 R339 R341 R346 R360 R361 R368 R398 R427 R428 R543 R553 R557 R560 R562 R569 R570 R620 R621 R623 R625 R626 R633 R636 R672 R673 R721 R748 R763 R764 R782-R785 R787 R788 R806 R809 R816-R818 R831 R958 R3096 R3108 R3112 R3114-R3117 = R: alternate symbols: (T:RC0603N;B:RC0603M)
R20 = R: alternate symbols: (T:RC0603N;B:RC0603M); signal model: DEFAULT_RESISTOR_0.001OHM_2_1
R45 = R: alternate symbols: (T:RC0603N;B:RC0603M); signal model: DEFAULT_RESISTOR_49.900000OHM_2_1
R46-R49 = R_0: signal model: DEFAULT_RESISTOR_49.900000OHM_2_1
R56 = R: signal model: DEFAULT_RESISTOR_4700OHM_2_1
R63-R65 R68 R77 R101 R134 R155 R174 R175 R181 R187 R194 R197 R198 R200 R232 R240 R270 R271 R306-R308 R310 R313 R318 R321 R323 R331-R334 R342 R359 R369 R370 R377 R429 R452-R456 R463 R512 R513 R528 R535 R537 R638 R663 R771 R772 R774 R789 R791 R807 R808 R810 R812-R814 R821 R2984 R2985 R2997 R3107 R3110 R3123 R3128 = R_0
R66 R420 = R: signal model: DEFAULT_RESISTOR_1000.000000OHM_2_1
R87 = R: alternate symbols: (T:RC0603N;B:RC0603M); signal model: DEFAULT_RESISTOR_1000.000000OHM_2_1
R129 R130 R136-R138 = R: signal model: DEFAULT_RESISTOR_51.000000OHM_2_1
R139 R711 = R: signal model: R_RC0402N_33_33
R246 R247 R383 = R: alternate symbols: (T:RC0805N;B:RC0805M)
R303 = R: alternate symbols: (T:RC1206N;B:RC1206M)
R316 R373 R391 R765 R766 R768 R773 R781 R786 R3129 = R_0: alternate symbols: (T:RC0603N;B:RC0603M)
R319 R320 R322 R324 R327 R329 R330 R335 = R_0: signal model: R_0_RC0603N_0_0
R336-R338 R340 R343 R344 R564 R565 R567 R568 = R: signal model: R_RC0603N_0_0
R371 R372 = R_0: signal model: DEFAULT_RESISTOR_0.001OHM_2_1
R393 = R: signal model: DEFAULT_RESISTOR_2.200000OHM_2_1
R397 = R: signal model: DEFAULT_RESISTOR_0.01OHM_2_1
SW1 = SW-2+2
TP2-TP8 TP10-TP14 TP16-TP18 TP20-TP23 TP25 TP35-TP40 TP43-TP45 = TP
U1 = 1356_SKL_ULT
U2 U6 U10 U17 U18 U27 = 5_SN74LVC1G08DCKR
U4 = 5_SN74LVC1G07DCK
U5 = 8_EMC1402
U8 U19 U25 = 5_APL3512
U9 = 48+1_RTL8105E/8111E
U11 = 24_EG24A005S
U12 U38-U40 = 5_APL3511
U13 U14 U2523 U2524 = 3_TPD2EUSB30DRTR
U16 = 48+1_ALC282
U21 U35 = APL591X_1
U22 = 128_IT8587E/DX
U23 = 5_SN74LVC1G06DCK
U24 = 8_MX25L4005AMC-12G
U29 = 32+3_APW8861QBI_6
U41 = 14+1_tps51117RGY_2
U42 = 8_W25Q64FV
U45 U50 U54 = 8+1_ISL95808
U56 U59 U67 = 8+1_TPS22965
U70 = 10+1_APW8804QB_0
U71 = 20+1_TPS51275/C
U95 = 24+1_GL834L
U103 = 40+1_ISL95857_1
U2525 U2527 = 8_AT24C02A
U2526 = 56+1_PS8625QFN56G
U2529 = 16+1_APW7228BRI
X1 X3 = OSC-4_7
X2 = CRYSTAL
X4 = OSC-4_4
X5 = OSC-2

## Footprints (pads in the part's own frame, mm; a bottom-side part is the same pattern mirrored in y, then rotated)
CAE630W570HN
  rect 3.5x1.6 smd: 1(-2.85,0) 2(2.85,0)
CC0201N
  rect 0.3x0.3 smd: 1(-0.275,0) 2(0.275,0)
CC0402N
  rect 0.55x0.5 smd: 1(-0.475,0) 2(0.475,0)
CC0603N
  rect 0.8x0.8 smd: 1(-0.75,0) 2(0.75,0)
CC0805N
  rect 1x1.2 smd: 1(-1,0) 2(1,0)
CC1206N
  rect 1.2x1.6 smd: 1(-1.6,0) 2(1.6,0)
CC1210N
  rect 1.3x2.6 smd: 1(-1.4,0) 2(1.4,0)
CC5750N
  rect 1.4x5 smd: 1(-2.75,0) 2(2.75,0)
CCP7343N
  rect 2.6x2.6 smd: 1(-3.05,0) 2(3.05,0)
DFN50P200X200-8N
  oval 0.5x0.25 smd: 1(-0.95,0.75) 2(-0.95,0.25) 3(-0.95,-0.25) 4(-0.95,-0.75) 5(0.95,-0.75) 6(0.95,-0.25) 7(0.95,0.25) 8(0.95,0.75)
  rect 0.9x1.6 smd: E1(0,0)
F1206N
  rect 1.3x1.8 smd: 1(-1.45,0) 2(1.45,0)
FB0603N
  rect 0.8x0.8 smd: 1(-0.75,0) 2(0.75,0)
FB0805N
  rect 1x1.2 smd: 1(-1,0) 2(1,0)
FIL_175P200X120-4L
  rect 0.6x0.7 smd: 1(-0.5,0.875) 2(-0.5,-0.875) 3(0.5,-0.875) 4(0.5,0.875)
LC3030DL
  rect 1.5x3.2 smd: 1(-1.05,0) 2(1.05,0)
LC4040L
  rect 4.4x1.6 smd: 1(0,1.4) 2(0,-1.4)
LC5452N
  rect 2x2.5 smd: 1(-2.1,0) 2(2.1,0)
LC6666N
  rect 2.3x3.3 smd: 1(-3.075,0) 2(3.075,0)
LC115102N
  rect 4.1x4.1 smd: 1(0,4.75) 2(0,-4.75)
LED1706N
  rect 0.8x0.8 smd: 1(0.85,0) 2(-0.85,0)
LQFP40P1600X1600-128N
  oval 1.3x0.2 smd: 1(-7.65,6.2) 2(-7.65,5.8) 3(-7.65,5.4) 4(-7.65,5) 5(-7.65,4.6) 6(-7.65,4.2) 7(-7.65,3.8) 8(-7.65,3.4) 9(-7.65,3) 10(-7.65,2.6) 11(-7.65,2.2) 12(-7.65,1.8) 13(-7.65,1.4) 14(-7.65,1) 15(-7.65,0.6) 16(-7.65,0.2) 17(-7.65,-0.2) 18(-7.65,-0.6) 19(-7.65,-1) 20(-7.65,-1.4) 21(-7.65,-1.8) 22(-7.65,-2.2) 23(-7.65,-2.6) 24(-7.65,-3) 25(-7.65,-3.4) 26(-7.65,-3.8) 27(-7.65,-4.2) 28(-7.65,-4.6) 29(-7.65,-5) 30(-7.65,-5.4) 31(-7.65,-5.8) 32(-7.65,-6.2) 65(7.65,-6.2) 66(7.65,-5.8) 67(7.65,-5.4) 68(7.65,-5) 69(7.65,-4.6) 70(7.65,-4.2) 71(7.65,-3.8) 72(7.65,-3.4) 73(7.65,-3) 74(7.65,-2.6) 75(7.65,-2.2) 76(7.65,-1.8) 77(7.65,-1.4) 78(7.65,-1) 79(7.65,-0.6) 80(7.65,-0.2) 81(7.65,0.2) 82(7.65,0.6) 83(7.65,1) 84(7.65,1.4) 85(7.65,1.8) 86(7.65,2.2) 87(7.65,2.6) 88(7.65,3) 89(7.65,3.4) 90(7.65,3.8) 91(7.65,4.2) 92(7.65,4.6) 93(7.65,5) 94(7.65,5.4) 95(7.65,5.8) 96(7.65,6.2)
  oval 0.2x1.3 smd: 33(-6.2,-7.65) 34(-5.8,-7.65) 35(-5.4,-7.65) 36(-5,-7.65) 37(-4.6,-7.65) 38(-4.2,-7.65) 39(-3.8,-7.65) 40(-3.4,-7.65) 41(-3,-7.65) 42(-2.6,-7.65) 43(-2.2,-7.65) 44(-1.8,-7.65) 45(-1.4,-7.65) 46(-1,-7.65) 47(-0.6,-7.65) 48(-0.2,-7.65) 49(0.2,-7.65) 50(0.6,-7.65) 51(1,-7.65) 52(1.4,-7.65) 53(1.8,-7.65) 54(2.2,-7.65) 55(2.6,-7.65) 56(3,-7.65) 57(3.4,-7.65) 58(3.8,-7.65) 59(4.2,-7.65) 60(4.6,-7.65) 61(5,-7.65) 62(5.4,-7.65) 63(5.8,-7.65) 64(6.2,-7.65) 97(6.2,7.65) 98(5.8,7.65) 99(5.4,7.65) 100(5,7.65) 101(4.6,7.65) 102(4.2,7.65) 103(3.8,7.65) 104(3.4,7.65) 105(3,7.65) 106(2.6,7.65) 107(2.2,7.65) 108(1.8,7.65) 109(1.4,7.65) 110(1,7.65) 111(0.6,7.65) 112(0.2,7.65) 113(-0.2,7.65) 114(-0.6,7.65) 115(-1,7.65) 116(-1.4,7.65) 117(-1.8,7.65) 118(-2.2,7.65) 119(-2.6,7.65) 120(-3,7.65) 121(-3.4,7.65) 122(-3.8,7.65) 123(-4.2,7.65) 124(-4.6,7.65) 125(-5,7.65) 126(-5.4,7.65) 127(-5.8,7.65) 128(-6.2,7.65)
MARK-D100D250
  round 1 smd: 1(0,0)
MIC_FOM6050MP3_190P
  round 1.3 hole 0.8: 1(-0.95,0) 2(0.95,0)
MTG230H400
  round 4 hole 2.3: 1(0,0)
MTG230H500
  round 5 hole 2.3: 1(0,0)
MTG230H600
  round 6 hole 2.3: 1(0,0)
MTG250H500
  round 5 hole 2.5: 1(0,0)
MTG340H580_TOP
  round 5.8 hole 3.4: 1(0,0)
MTG380H500
  round 5 hole 3.8: 1(0,0)
OSC120P150X670-4L
  rect 0.6x0.9 smd: 1(-0.6,3.3) 2(-0.6,-3.3) 3(0.6,-3.3) 4(0.6,3.3)
OSC127P200X600-2L
  rect 0.6x2.5 smd: 1(-0.6,4.98) 2(0.6,4.98)
OSC170P320X250-4N
  rect 1.4x1.15 smd: 1(-1.1,-0.85) 2(1.1,-0.85) 3(1.1,0.85) 4(-1.1,0.85)
PQFP50P365X365-14N
  oval 0.7x0.28 smd: 1(-1.775,-0.75) 7(1.775,-0.75) 8(1.775,0.75) 14(-1.775,0.75)
  oval 0.28x0.7 smd: 2(-1,-1.775) 3(-0.5,-1.775) 4(0,-1.775) 5(0.5,-1.775) 6(1,-1.775) 9(1,1.775) 10(0.5,1.775) 11(0,1.775) 12(-0.5,1.775) 13(-1,1.775)
  rect 2.05x2.05 smd: E1(0,0)
QFN40P300X300-20N
  oval 0.6x0.2 smd: 1(-1.4,0.8) 2(-1.4,0.4) 3(-1.4,0) 4(-1.4,-0.4) 5(-1.4,-0.8) 11(1.4,-0.8) 12(1.4,-0.4) 13(1.4,0) 14(1.4,0.4) 15(1.4,0.8)
  oval 0.2x0.6 smd: 6(-0.8,-1.4) 7(-0.4,-1.4) 8(0,-1.4) 9(0.4,-1.4) 10(0.8,-1.4) 16(0.8,1.4) 17(0.4,1.4) 18(0,1.4) 19(-0.4,1.4) 20(-0.8,1.4)
  rect 1.8x1.8 smd: E1(0,0)
QFN40P400X400-35N
  oval 0.2x0.8 smd: 1(-1.4,-2.05) 2(-1,-2.05) 3(-0.6,-2.05) 4(-0.2,-2.05) 5(0.2,-2.05) 6(0.6,-2.05) 7(1,-2.05) 8(1.4,-2.05) 17(1.4,2.05) 18(1,2.05) 19(0.6,2.05) 20(0.2,2.05) 21(-0.2,2.05) 22(-0.6,2.05) 23(-1,2.05) 24(-1.4,2.05)
  oval 0.8x0.2 smd: 9(2.05,-1.4) 10(2.05,-1) 11(2.05,-0.6) 12(2.05,-0.2) 13(2.05,0.2) 14(2.05,0.6) 15(2.05,1) 16(2.05,1.4) 25(-2.05,1.4) 26(-2.05,1) 27(-2.05,0.6) 28(-2.05,0.2) 29(-2.05,-0.2) 30(-2.05,-0.6) 31(-2.05,-1) 32(-2.05,-1.4)
  rect 1.1x1.4 smd: 33(-0.817,0.697)
  rect 1.1x1.1 smd: 34(-0.817,-0.836)
  rect 1.4x2.8 smd: 35(0.749,0.014)
QFN40P600X600-48AN
  oval 0.7x0.2 smd: 1(-2.9,2.2) 2(-2.9,1.8) 3(-2.9,1.4) 4(-2.9,1) 5(-2.9,0.6) 6(-2.9,0.2) 7(-2.9,-0.2) 8(-2.9,-0.6) 9(-2.9,-1) 10(-2.9,-1.4) 11(-2.9,-1.8) 12(-2.9,-2.2) 25(2.9,-2.2) 26(2.9,-1.8) 27(2.9,-1.4) 28(2.9,-1) 29(2.9,-0.6) 30(2.9,-0.2) 31(2.9,0.2) 32(2.9,0.6) 33(2.9,1) 34(2.9,1.4) 35(2.9,1.8) 36(2.9,2.2)
  oval 0.2x0.7 smd: 13(-2.2,-2.9) 14(-1.8,-2.9) 15(-1.4,-2.9) 16(-1,-2.9) 17(-0.6,-2.9) 18(-0.2,-2.9) 19(0.2,-2.9) 20(0.6,-2.9) 21(1,-2.9) 22(1.4,-2.9) 23(1.8,-2.9) 24(2.2,-2.9) 37(2.2,2.9) 38(1.8,2.9) 39(1.4,2.9) 40(1,2.9) 41(0.6,2.9) 42(0.2,2.9) 43(-0.2,2.9) 44(-0.6,2.9) 45(-1,2.9) 46(-1.4,2.9) 47(-1.8,2.9) 48(-2.2,2.9)
  rect 3.6x4.05 smd: E1(0,0)
QFN40P600X600-48N
  oval 0.7x0.2 smd: 1(-2.9,2.2) 2(-2.9,1.8) 3(-2.9,1.4) 4(-2.9,1) 5(-2.9,0.6) 6(-2.9,0.2) 7(-2.9,-0.2) 8(-2.9,-0.6) 9(-2.9,-1) 10(-2.9,-1.4) 11(-2.9,-1.8) 12(-2.9,-2.2) 25(2.9,-2.2) 26(2.9,-1.8) 27(2.9,-1.4) 28(2.9,-1) 29(2.9,-0.6) 30(2.9,-0.2) 31(2.9,0.2) 32(2.9,0.6) 33(2.9,1) 34(2.9,1.4) 35(2.9,1.8) 36(2.9,2.2)
  oval 0.2x0.7 smd: 13(-2.2,-2.9) 14(-1.8,-2.9) 15(-1.4,-2.9) 16(-1,-2.9) 17(-0.6,-2.9) 18(-0.2,-2.9) 19(0.2,-2.9) 20(0.6,-2.9) 21(1,-2.9) 22(1.4,-2.9) 23(1.8,-2.9) 24(2.2,-2.9) 37(2.2,2.9) 38(1.8,2.9) 39(1.4,2.9) 40(1,2.9) 41(0.6,2.9) 42(0.2,2.9) 43(-0.2,2.9) 44(-0.6,2.9) 45(-1,2.9) 46(-1.4,2.9) 47(-1.8,2.9) 48(-2.2,2.9)
  rect 4.3x4.3 smd: E1(0,0)
QFN40P700X700-56AN
  oval 0.7x0.2 smd: 1(-3.4,2.6) 2(-3.4,2.2) 3(-3.4,1.8) 4(-3.4,1.4) 5(-3.4,1) 6(-3.4,0.6) 7(-3.4,0.2) 8(-3.4,-0.2) 9(-3.4,-0.6) 10(-3.4,-1) 11(-3.4,-1.4) 12(-3.4,-1.8) 13(-3.4,-2.2) 14(-3.4,-2.6) 29(3.4,-2.6) 30(3.4,-2.2) 31(3.4,-1.8) 32(3.4,-1.4) 33(3.4,-1) 34(3.4,-0.6) 35(3.4,-0.2) 36(3.4,0.2) 37(3.4,0.6) 38(3.4,1) 39(3.4,1.4) 40(3.4,1.8) 41(3.4,2.2) 42(3.4,2.6)
  oval 0.2x0.7 smd: 15(-2.6,-3.4) 16(-2.2,-3.4) 17(-1.8,-3.4) 18(-1.4,-3.4) 19(-1,-3.4) 20(-0.6,-3.4) 21(-0.2,-3.4) 22(0.2,-3.4) 23(0.6,-3.4) 24(1,-3.4) 25(1.4,-3.4) 26(1.8,-3.4) 27(2.2,-3.4) 28(2.6,-3.4) 43(2.6,3.4) 44(2.2,3.4) 45(1.8,3.4) 46(1.4,3.4) 47(1,3.4) 48(0.6,3.4) 49(0.2,3.4) 50(-0.2,3.4) 51(-0.6,3.4) 52(-1,3.4) 53(-1.4,3.4) 54(-1.8,3.4) 55(-2.2,3.4) 56(-2.6,3.4)
  rect 4.1x4.8 smd: E1(0,0)
QFN50P400X400-24BN
  oval 0.8x0.28 smd: 1(-2,1.25) 2(-2,0.75) 3(-2,0.25) 4(-2,-0.25) 5(-2,-0.75) 6(-2,-1.25) 13(2,-1.25) 14(2,-0.75) 15(2,-0.25) 16(2,0.25) 17(2,0.75) 18(2,1.25)
  oval 0.28x0.8 smd: 7(-1.25,-2) 8(-0.75,-2) 9(-0.25,-2) 10(0.25,-2) 11(0.75,-2) 12(1.25,-2) 19(1.25,2) 20(0.75,2) 21(0.25,2) 22(-0.25,2) 23(-0.75,2) 24(-1.25,2)
  rect 2.5x2.5 smd: E1(0,0)
RC0201N
  rect 0.3x0.3 smd: 1(-0.275,0) 2(0.275,0)
RC0402L
  custom 0.125x0.125 smd: 1(-0.45,0) 2(0.45,0)
RC0402N
  rect 0.55x0.5 smd: 1(-0.475,0) 2(0.475,0)
RC0603N
  rect 0.8x0.8 smd: 1(-0.75,0) 2(0.75,0)
RC0805N
  rect 1x1.2 smd: 1(-1,0) 2(1,0)
RC1206N
  rect 1.2x1.6 smd: 1(-1.6,0) 2(1.6,0)
RC2512N
  rect 1.65x3.68 smd: 1(-2.855,0) 2(2.855,0)
SKL_42X24_P65_1356_KOZ
  round 0.356 smd: A3(19.349,-11.314) A70(-19.852,-11.314) B2(19.832,-10.832) B71(-20.314,-10.852) BA1(20.314,10.852) BA71(-20.314,10.852) BB2(19.852,11.314) BB70(-19.852,11.314) C1(20.314,-10.349)
  round 0.33 smd: A4(18.699,-11.314) A69(-19.202,-11.314) AY1(20.314,10.202) AY71(-20.314,10.202) B3(19.197,-10.679) B70(-19.685,-10.685) BA2(19.685,10.685) BA70(-19.685,10.685) BB3(19.202,11.314) BB69(-19.202,11.314) C2(19.679,-10.197) C71(-20.314,-10.202) D1(20.314,-9.699)
  round 0.305 smd: A5(18.048,-11.314) A68(-18.552,-11.314) AA2(19.339,-0.511) AA4(18.363,-0.511) AA63(-15.112,-0.596) AA64(-15.763,-0.596) AA65(-16.413,-0.596) AA66(-17.063,-0.596) AA67(-17.713,-0.596) AA68(-18.364,-0.596) AA69(-19.014,-0.596) AA70(-19.664,-0.596) AA71(-20.314,-0.596) AB4(18.363,0.152) AB6(17.585,-0.133) AB7(16.935,-0.133) AB8(16.285,-0.133) AB9(15.635,-0.133) AB10(14.984,-0.133) AB11(14.334,-0.133) AB12(13.684,-0.133) AB13(13.034,-0.133) AB15(12.188,-0.009) AB16(11.538,-0.009) AB17(10.888,-0.009) AB18(10.237,-0.009) AB19(9.587,-0.009) AB20(8.937,-0.009) AB21(8.287,-0.009) AB62(-14.644,-0.138) AC3(18.689,0.815) AC63(-15.112,0.319) AC64(-15.763,0.319) AC65(-16.413,0.319) AC66(-17.063,0.319) AC67(-17.713,0.319) AC68(-18.364,0.319) AC69(-19.014,0.319) AC70(-19.664,0.319) AC71(-20.314,0.319) AD4(18.363,1.478) AD6(17.585,0.934) AD7(16.935,0.934) AD8(16.285,0.934) AD9(15.635,0.934) AD10(14.984,0.934) AD11(14.334,0.934) AD12(13.684,0.934) AD13(13.034,0.934) AD15(12.188,0.829) AD16(11.538,0.829) AD17(10.888,0.829) AD18(10.237,0.829) AD19(9.587,0.829) AD20(8.937,0.829) AD21(8.287,0.829) AD62(-14.644,0.776) AE62(-14.644,1.69) AE63(-15.112,1.233) AE64(-15.763,1.233) AE65(-16.413,1.233) AE66(-17.063,1.233) AE67(-17.713,1.233) AE68(-18.364,1.233) AE69(-19.014,1.233) AF2(19.339,2.141) AF4(18.363,2.141) AF6(17.585,2.001) AF7(16.935,2.001) AF8(16.285,2.001) AF9(15.635,2.001) AF10(14.984,2.001) AF11(14.334,2.001) AF12(13.684,2.001) AF13(13.034,2.001) AF15(12.188,1.668) AF16(11.538,1.668) AF17(10.888,1.668) AF18(10.237,1.668) AF19(9.587,1.668) AF20(8.937,1.668) AF21(8.287,1.668) AF63(-15.112,2.148) AF64(-15.763,2.148) AF65(-16.413,2.148) AF66(-17.063,2.148) AF67(-17.713,2.148) AF68(-18.364,1.939) AF69(-19.014,1.939) AG4(18.363,2.804) AG15(12.188,2.506) AG16(11.538,2.506) AG17(10.888,2.506) AG18(10.237,2.506) AG19(9.587,2.506) AG20(8.937,2.506) AG21(8.287,2.506) AG62(-14.644,2.605) AG69(-18.689,2.602) AH3(18.689,3.467) AH6(17.585,3.067) AH7(16.935,3.067) AH8(16.285,3.067) AH9(15.635,3.067) AH10(14.984,3.067) AH11(14.334,3.067) AH12(13.684,3.067) AH13(13.034,3.067) AH63(-15.112,3.062) AH64(-15.763,3.062) AH65(-16.413,3.062) AH66(-17.063,3.062) AH67(-17.713,3.062) AJ4(18.363,4.13) AJ15(12.188,3.344) AJ16(11.538,3.344) AJ17(10.888,3.344) AJ18(10.237,3.344) AJ19(9.587,3.344) AJ20(8.937,3.344) AJ21(8.287,3.344) AJ62(-14.644,3.519) AK6(17.585,4.007) AK7(16.935,4.007) AK8(16.285,4.007) AK9(15.635,4.007) AK10(14.984,4.007) AK11(14.334,4.007) AK12(13.684,4.007) AK13(13.034,4.007) AK15(12.188,4.182) AK16(11.538,4.182) AK17(10.888,4.182) AK18(10.237,4.182) AK19(9.587,4.182) AK20(8.937,4.182) AK21(8.287,4.182) AK22(7.596,4.009) AK23(6.681,4.009) AK25(5.767,4.009) AK27(4.852,4.009) AK28(3.938,4.009) AK30(3.024,4.009) AK32(2.109,4.009) AK33(1.195,4.009) AK35(0.28,4.009) AK37(-0.634,4.009) AK38(-1.548,4.009) AK40(-2.463,4.009) AK42(-3.377,4.009) AK43(-4.292,4.009) AK45(-5.206,4.009) AK46(-6.12,4.009) AK48(-7.035,4.009) AK50(-7.949,4.009) AK52(-8.864,4.009) AK53(-9.778,4.009) AK55(-10.692,4.009) AK56(-11.607,4.009) AK58(-12.521,4.009) AK60(-13.436,4.009) AK62(-14.46,4.144) AK63(-15.112,3.976) AK64(-15.763,3.976) AK65(-16.413,3.976) AK66(-17.063,3.976) AK67(-17.713,3.976) AK68(-18.364,3.829) AK69(-19.339,3.829) AL2(19.339,4.793) AL4(18.363,4.793) AL23(7.138,4.474) AL25(6.224,4.474) AL27(5.31,4.474) AL28(4.395,4.474) AL30(3.481,4.474) AL32(2.566,4.474) AL33(1.652,4.474) AL35(0.738,4.474) AL37(-0.177,4.474) AL38(-1.091,4.474) AL40(-2.006,4.474) AL42(-2.92,4.474) AL43(-3.834,4.474) AL45(-4.749,4.474) AL46(-5.663,4.474) AL48(-6.578,4.474) AL50(-7.492,4.474) AL52(-8.406,4.474) AL53(-9.321,4.474) AL55(-10.235,4.474) AL56(-11.15,4.474) AL58(-12.064,4.474) AL60(-12.978,4.474) AL61(-13.893,4.474) AL63(-15.112,4.845) AL64(-15.763,4.845) AL65(-16.413,4.845) AL66(-17.063,4.845) AM4(18.363,5.456) AM5(17.654,4.946) AM7(16.74,4.946) AM8(15.825,4.946) AM10(14.911,4.946) AM11(13.996,4.946) AM13(13.082,4.946) AM15(12.168,4.946) AM16(11.253,4.946) AM18(10.339,4.946) AM20(9.424,4.946) AM21(8.51,4.946) AM22(7.596,4.946) AM23(6.681,4.946) AM25(5.767,4.946) AM27(4.852,4.946) AM28(3.938,4.946) AM30(3.024,4.946) AM32(2.109,4.946) AM33(1.195,4.946) AM35(0.28,4.946) AM37(-0.634,4.946) AM38(-1.548,4.946) AM40(-2.463,4.946) AM42(-3.377,4.946) AM43(-4.292,4.946) AM45(-5.206,4.946) AM46(-6.12,4.946) AM48(-7.035,4.946) AM50(-7.949,4.946) AM52(-8.864,4.946) AM53(-9.778,4.946) AM55(-10.692,4.946) AM56(-11.607,4.946) AM58(-12.521,4.946) AM60(-13.436,4.946) AM61(-14.35,4.946) AM68(-18.039,5.056) AM69(-18.689,5.056) AN3(18.689,6.119) AN5(17.654,5.597) AN7(16.74,5.597) AN8(15.825,5.597) AN10(14.911,5.597) AN11(13.996,5.597) AN13(13.082,5.597) AN15(12.168,5.597) AN16(11.253,5.597) AN18(10.339,5.597) AN20(9.424,5.597) AN21(8.51,5.597) AN22(7.596,5.597) AN23(6.681,5.597) AN25(5.767,5.597) AN27(4.852,5.597) AN28(3.938,5.597) AN30(3.024,5.597) AN32(2.109,5.597) AN33(1.195,5.597) AN35(0.28,5.597) AN37(-0.634,5.597) AN38(-1.548,5.597) AN40(-2.463,5.597) AN42(-3.377,5.597) AN43(-4.292,5.597) AN45(-5.206,5.597) AN46(-6.12,5.597) AN48(-7.035,5.597) AN50(-7.949,5.597) AN52(-8.864,5.597) AN53(-9.778,5.597) AN55(-10.692,5.597) AN56(-11.607,5.597) AN58(-12.521,5.597) AN60(-13.436,5.597) AN61(-14.35,5.597) AN63(-15.264,5.597) AN65(-16.179,5.597) AN66(-17.093,5.597) AN68(-18.364,5.719) AN69(-19.014,5.719) AP4(18.363,6.782) AP5(17.654,6.247) AP7(16.74,6.247) AP8(15.825,6.247) AP10(14.911,6.247) AP11(13.996,6.247) AP13(13.082,6.247) AP15(12.168,6.247) AP16(11.253,6.247) AP18(10.339,6.247) AP20(9.424,6.247) AP21(8.51,6.247) AP22(7.596,6.247) AP23(6.681,6.247) AP25(5.767,6.247) AP27(4.852,6.247) AP28(3.938,6.247) AP30(3.024,6.247) AP32(2.109,6.247) AP33(1.195,6.247) AP35(0.28,6.247) AP37(-0.634,6.247) AP38(-1.548,6.247) AP40(-2.463,6.247) AP42(-3.377,6.247) AP43(-4.292,6.247) AP45(-5.206,6.247) AP46(-6.12,6.247) AP48(-7.035,6.247) AP50(-7.949,6.247) AP52(-8.864,6.247) AP53(-9.778,6.247) AP55(-10.692,6.247) AP56(-11.607,6.247) AP58(-12.521,6.247) AP60(-13.436,6.247) AP61(-14.35,6.247) AP63(-15.264,6.247) AP65(-16.179,6.247) AP66(-17.093,6.247) AP68(-18.039,6.332) AP70(-19.258,6.332) AR5(17.654,6.897) AR7(16.74,6.897) AR8(15.825,6.897) AR10(14.911,6.897) AR11(13.996,6.897) AR13(13.082,6.897) AR15(12.168,6.897) AR16(11.253,6.897) AR18(10.339,6.897) AR20(9.424,6.897) AR21(8.51,6.897) AR22(7.596,6.897) AR23(6.681,6.897) AR25(5.767,6.897) AR27(4.852,6.897) AR28(3.938,6.897) AR30(3.024,6.897) AR32(2.109,6.897) AR33(1.195,6.897) AR35(0.28,6.897) AR37(-0.634,6.897) AR38(-1.548,6.897) AR40(-2.463,6.897) AR42(-3.377,6.897) AR43(-4.292,6.897) AR45(-5.206,6.897) AR46(-6.12,6.897) AR48(-7.035,6.897) AR50(-7.949,6.897) AR52(-8.864,6.897) AR53(-9.778,6.897) AR55(-10.692,6.897) AR56(-11.607,6.897) AR58(-12.521,6.897) AR60(-13.436,6.897) AR61(-14.35,6.897) AR63(-15.264,6.897) AR65(-16.179,6.897) AR66(-17.093,6.897) AR68(-18.364,6.945) AR69(-19.014,6.945) AT2(19.339,7.445) AT4(18.363,7.445) AT5(17.654,7.547) AT7(16.74,7.547) AT8(15.825,7.547) AT10(14.911,7.547) AT11(13.996,7.547) AT13(13.082,7.547) AT15(12.168,7.547) AT16(11.253,7.547) AT18(10.339,7.547) AT20(9.424,7.547) AT21(8.51,7.547) AT22(7.596,7.547) AT23(6.681,7.547) AT25(5.767,7.547) AT27(4.852,7.547) AT28(3.938,7.547) AT30(3.024,7.547) AT32(2.109,7.547) AT33(1.195,7.547) AT35(0.28,7.547) AT37(-0.634,7.547) AT38(-1.548,7.547) AT40(-2.463,7.547) AT42(-3.377,7.547) AT43(-4.292,7.547) AT45(-5.206,7.547) AT46(-6.12,7.547) AT48(-7.035,7.547) AT50(-7.949,7.547) AT52(-8.864,7.547) AT53(-9.778,7.547) AT55(-10.692,7.547) AT56(-11.607,7.547) AT58(-12.521,7.547) AT60(-13.436,7.547) AT61(-14.35,7.547) AT63(-15.264,7.547) AT65(-16.179,7.547) AT66(-17.093,7.547) AT68(-18.039,7.509) AT69(-18.689,7.509) AU4(18.363,8.108) AU5(17.654,8.198) AU7(16.74,8.198) AU8(15.825,8.198) AU10(14.911,8.198) AU11(13.996,8.198) AU13(13.082,8.198) AU15(12.168,8.198) AU16(11.253,8.198) AU18(10.339,8.198) AU20(9.424,8.198) AU21(8.51,8.198) AU22(7.596,8.198) AU23(6.681,8.198) AU25(5.767,8.198) AU27(4.852,8.198) AU28(3.938,8.198) AU30(3.024,8.198) AU32(2.109,8.198) AU33(1.195,8.198) AU35(0.28,8.198) AU37(-0.634,8.198) AU38(-1.548,8.198) AU40(-2.463,8.198) AU42(-3.377,8.198) AU43(-4.292,8.198) AU45(-5.206,8.198) AU46(-6.12,8.198) AU48(-7.035,8.198) AU50(-7.949,8.198) AU52(-8.864,8.198) AU53(-9.778,8.198) AU55(-10.692,8.198) AU56(-11.607,8.198) AU58(-12.521,8.198) AU60(-13.436,8.198) AU61(-14.35,8.198) AU63(-15.264,8.198) AU65(-16.179,8.198) AU66(-17.093,8.198) AV3(18.689,8.799) AV68(-18.029,8.711) AV69(-19.014,8.901) AV70(-19.664,8.901) AW1(20.314,9.551) AW5(17.781,8.911) AW6(17.13,9.038) AW7(16.564,9.363) AW8(15.986,9.038) AW9(15.416,9.363) AW10(14.753,9.038) AW11(14.143,9.363) AW12(13.565,9.038) AW13(12.995,9.363) AW14(12.332,9.038) AW15(11.723,9.363) AW16(11.145,9.038) AW17(10.575,9.363) AW18(9.912,9.038) AW20(9.302,9.363) AW21(8.724,9.038) AW22(8.154,9.363) AW23(7.466,9.038) AW25(6.828,9.363) AW26(6.264,9.038) AW27(5.601,9.363) AW28(4.988,9.038) AW29(4.374,9.363) AW30(3.711,9.038) AW31(3.148,9.363) AW32(2.485,9.038) AW33(1.847,9.363) AW34(1.283,9.038) AW35(0.62,9.363) AW36(0.007,9.038) AW37(-0.607,9.363) AW38(-1.269,9.038) AW39(-1.833,9.363) AW41(-2.471,9.038) AW42(-3.108,9.363) AW43(-3.672,9.038) AW44(-4.335,9.363) AW45(-4.949,9.038) AW46(-5.562,9.363) AW47(-6.163,9.038) AW48(-6.727,9.363) AW49(-7.355,9.038) AW50(-7.984,9.363) AW51(-8.548,9.038) AW52(-9.149,9.363) AW53(-9.762,9.038) AW54(-10.375,9.363) AW55(-11.038,9.038) AW56(-11.602,9.363) AW57(-12.24,9.038) AW59(-12.877,9.363) AW60(-13.441,9.038) AW61(-14.104,9.363) AW62(-14.718,9.038) AW63(-15.331,9.363) AW64(-15.994,9.038) AW65(-16.558,9.363) AW66(-17.093,8.9) AW67(-18.018,9.371) AW68(-18.622,9.622) AW69(-19.267,9.536) AW70(-19.685,10.035) AW71(-20.314,9.551) AY2(19.685,10.034) AY3(19.028,10.028) AY4(18.274,10.043) AY5(17.665,9.689) AY8(15.986,9.689) AY12(13.565,9.689) AY16(11.145,9.689) AY21(8.724,9.689) AY26(6.264,9.689) AY27(5.601,10.014) AY29(4.374,10.014) AY30(3.711,9.689) AY34(1.283,9.689) AY35(0.62,10.014) AY37(-0.607,10.014) AY38(-1.269,9.689) AY43(-3.672,9.689) AY44(-4.335,10.014) AY46(-5.562,10.014) AY47(-6.163,9.689) AY51(-8.548,9.689) AY52(-9.149,10.014) AY54(-10.375,10.014) AY55(-11.038,9.689) AY60(-13.441,9.689) AY61(-14.104,10.014) AY63(-15.331,10.014) AY64(-15.994,9.689) AY66(-17.221,9.689) AY68(-18.535,10.267) B5(18.048,-10.664) B6(17.467,-10.339) B10(14.989,-10.339) B14(12.511,-10.339) B18(10.033,-10.339) B22(7.555,-10.339) B26(5.077,-10.339) B30(2.599,-10.339) B34(0.121,-10.339) B39(-2.357,-10.339) B44(-4.835,-10.339) B48(-7.313,-10.339) B53(-9.791,-10.339) B58(-12.269,-10.339) B62(-14.747,-10.339) B66(-17.226,-10.339) B69(-19.035,-10.685) BA3(19.035,10.685) BA5(17.715,10.626) BA8(15.986,10.339) BA12(13.565,10.339) BA16(11.145,10.339) BA21(8.724,10.339) BA23(7.466,10.258) BA28(4.988,10.258) BA32(2.485,10.258) BA36(0.007,10.258) BA41(-2.471,10.258) BA45(-4.949,10.258) BA49(-7.355,10.339) BA53(-9.762,10.258) BA57(-12.24,10.258) BA62(-14.718,10.258) BA68(-19.035,10.685) BB4(18.551,11.314) BB68(-18.552,11.314) C4(18.615,-10.336) C5(18.048,-10.014) C7(16.791,-10.014) C8(16.228,-10.339) C9(15.664,-10.014) C11(14.313,-10.014) C12(13.75,-10.339) C13(13.186,-10.014) C15(11.835,-10.014) C16(11.272,-10.339) C17(10.708,-10.014) C19(9.357,-10.014) C20(8.794,-10.339) C21(8.23,-10.014) C23(6.879,-10.014) C24(6.316,-10.339) C25(5.752,-10.014) C27(4.401,-10.014) C28(3.838,-10.339) C29(3.274,-10.014) C31(1.923,-10.014) C32(1.36,-10.339) C33(0.796,-10.014) C36(-0.555,-10.014) C37(-1.118,-10.339) C38(-1.682,-10.014) C40(-3.033,-10.014) C41(-3.596,-10.339) C42(-4.16,-10.014) C45(-5.511,-10.014) C46(-6.074,-10.339) C47(-6.638,-10.014) C50(-7.989,-10.014) C51(-8.552,-10.339) C52(-9.116,-10.014) C54(-10.467,-10.014) C55(-11.03,-10.339) C56(-11.594,-10.014) C59(-12.945,-10.014) C60(-13.508,-10.339) C61(-14.072,-10.014) C63(-15.423,-10.014) C64(-15.987,-10.339) C65(-16.55,-10.014) C67(-18.485,-10.299) C68(-18.622,-9.622) C70(-19.685,-10.034) D3(19.339,-9.608) D4(18.691,-9.669) D5(18.09,-9.363) D6(17.441,-9.323) D7(16.791,-9.363) D8(16.228,-9.689) D9(15.664,-9.363) D10(14.989,-9.323) D11(14.313,-9.363) D12(13.75,-9.689) D13(13.186,-9.363) D14(12.511,-9.323) D15(11.835,-9.363) D16(11.272,-9.689) D17(10.708,-9.363) D18(10.033,-9.323) D19(9.357,-9.363) D20(8.794,-9.689) D21(8.23,-9.363) D22(7.555,-9.323) D23(6.879,-9.363) D24(6.316,-9.689) D25(5.752,-9.363) D26(5.077,-9.323) D27(4.401,-9.363) D28(3.838,-9.689) D29(3.274,-9.363) D30(2.599,-9.323) D31(1.923,-9.363) D32(1.36,-9.689) D33(0.796,-9.363) D34(0.121,-9.323) D36(-0.555,-9.363) D37(-1.118,-9.689) D38(-1.682,-9.363) D39(-2.357,-9.323) D40(-3.033,-9.363) D41(-3.596,-9.689) D42(-4.16,-9.363) D44(-4.835,-9.323) D45(-5.511,-9.363) D46(-6.074,-9.689) D47(-6.638,-9.363) D48(-7.313,-9.323) D50(-7.989,-9.363) D51(-8.552,-9.689) D52(-9.116,-9.363) D53(-9.791,-9.323) D54(-10.467,-9.363) D55(-11.03,-9.689) D56(-11.594,-9.363) D58(-12.269,-9.323) D59(-12.945,-9.363) D60(-13.508,-9.689) D61(-14.072,-9.363) D62(-14.747,-9.323) D63(-15.423,-9.363) D64(-15.987,-9.689) D65(-16.55,-9.363) D66(-17.226,-9.323) D67(-17.899,-10.014) D68(-19.267,-9.535) D69(-18.562,-8.971) D71(-20.314,-9.551) E1(20.314,-9.04) E2(19.664,-9.04) E3(19.014,-9.04) E5(17.654,-8.591) E6(16.74,-8.591) E8(15.825,-8.591) E10(14.911,-8.591) E11(13.996,-8.591) E13(13.082,-8.591) E15(12.168,-8.591) E16(11.253,-8.591) E18(10.339,-8.591) E20(9.424,-8.591) E21(8.51,-8.591) E22(7.596,-8.591) E23(6.681,-8.591) E25(5.767,-8.591) E27(4.852,-8.591) E28(3.938,-8.591) E30(3.024,-8.591) E32(2.109,-8.591) E33(1.195,-8.591) E35(0.28,-8.591) E37(-0.634,-8.591) E38(-1.548,-8.591) E40(-2.463,-8.591) E42(-3.377,-8.591) E43(-4.292,-8.591) E45(-5.206,-8.591) E46(-6.12,-8.591) E48(-7.035,-8.591) E50(-7.949,-8.591) E52(-8.864,-8.591) E53(-9.778,-8.591) E55(-10.692,-8.591) E56(-11.607,-8.591) E58(-12.521,-8.591) E60(-13.436,-8.591) E61(-14.35,-8.591) E63(-15.315,-8.655) E65(-16.331,-8.655) E66(-17.347,-8.655) E68(-17.899,-9.363) F2(19.339,-8.466) F4(18.363,-8.466) F5(17.654,-7.941) F6(16.74,-7.941) F8(15.825,-7.941) F10(14.911,-7.941) F11(13.996,-7.941) F13(13.082,-7.941) F15(12.168,-7.941) F16(11.253,-7.941) F18(10.339,-7.941) F20(9.424,-7.941) F21(8.51,-7.941) F22(7.596,-7.941) F23(6.681,-7.941) F25(5.767,-7.941) F27(4.852,-7.941) F28(3.938,-7.941) F30(3.024,-7.941) F32(2.109,-7.941) F33(1.195,-7.941) F35(0.28,-7.941) F37(-0.634,-7.941) F38(-1.548,-7.941) F40(-2.463,-7.941) F42(-3.377,-7.941) F43(-4.292,-7.941) F45(-5.206,-7.941) F46(-6.12,-7.941) F48(-7.035,-7.941) F50(-7.949,-7.941) F52(-8.864,-7.941) F53(-9.778,-7.941) F55(-10.692,-7.941) F56(-11.607,-7.941) F58(-12.521,-7.941) F60(-13.436,-7.941) F61(-14.35,-7.941) F63(-15.315,-8.005) F65(-16.331,-8.005) F66(-17.347,-8.005) F68(-18.562,-8.32) G4(18.363,-7.803) G5(17.654,-7.291) G6(16.74,-7.291) G8(15.825,-7.291) G10(14.911,-7.291) G11(13.996,-7.291) G13(13.082,-7.291) G15(12.168,-7.291) G16(11.253,-7.291) G18(10.339,-7.291) G20(9.424,-7.291) G21(8.51,-7.291) G22(7.596,-7.291) G23(6.681,-7.291) G25(5.767,-7.291) G27(4.852,-7.291) G28(3.938,-7.291) G30(3.024,-7.291) G32(2.109,-7.291) G33(1.195,-7.291) G35(0.28,-7.291) G37(-0.634,-7.291) G38(-1.548,-7.291) G40(-2.463,-7.291) G42(-3.377,-7.291) G43(-4.292,-7.291) G45(-5.206,-7.291) G46(-6.12,-7.291) G48(-7.035,-7.291) G50(-7.949,-7.291) G52(-8.864,-7.291) G53(-9.778,-7.291) G55(-10.692,-7.291) G56(-11.607,-7.291) G58(-12.521,-7.291) G60(-13.436,-7.291) G61(-14.35,-7.291) G63(-15.315,-7.354) G65(-16.331,-7.354) G66(-17.347,-7.354) G68(-18.364,-7.66) G69(-19.014,-7.66) H3(18.689,-7.14) H5(17.654,-6.641) H6(16.74,-6.641) H8(15.825,-6.641) H10(14.911,-6.641) H11(13.996,-6.641) H13(13.082,-6.641) H15(12.168,-6.641) H16(11.253,-6.641) H18(10.339,-6.641) H20(9.424,-6.641) H21(8.51,-6.641) H63(-15.315,-6.704) H65(-16.331,-6.704) H66(-17.347,-6.704) H69(-18.689,-7.096) J4(18.363,-6.477) J5(17.654,-5.99) J6(16.74,-5.99) J8(15.825,-5.99) J10(14.911,-5.99) J11(13.996,-5.99) J13(13.082,-5.99) J22(7.138,-6.827) J23(6.224,-6.827) J25(5.31,-6.827) J27(4.395,-6.827) J28(3.481,-6.827) J30(2.566,-6.827) J32(1.652,-6.827) J33(0.738,-6.827) J35(-0.177,-6.827) J37(-1.091,-6.827) J38(-2.006,-6.827) J40(-2.92,-6.827) J42(-3.834,-6.827) J43(-4.749,-6.827) J45(-5.663,-6.827) J46(-6.578,-6.827) J48(-7.492,-6.827) J50(-8.406,-6.827) J52(-9.321,-6.827) J53(-10.235,-6.827) J55(-11.15,-6.827) J56(-12.064,-6.827) J58(-12.978,-6.827) J60(-13.893,-6.827) J68(-18.362,-6.52) K15(12.188,-5.876) K16(11.538,-5.876) K17(10.888,-5.876) K18(10.237,-5.876) K19(9.587,-5.876) K20(8.937,-5.876) K21(8.287,-5.876) K22(7.596,-6.362) K23(6.681,-6.362) K25(5.767,-6.362) K27(4.852,-6.362) K28(3.938,-6.362) K30(3.024,-6.362) K32(2.109,-6.362) K33(1.195,-6.362) K35(0.28,-6.362) K37(-0.634,-6.362) K38(-1.548,-6.362) K40(-2.463,-6.362) K42(-3.377,-6.362) K43(-4.292,-6.362) K45(-5.206,-6.362) K46(-6.12,-6.362) K48(-7.035,-6.362) K50(-7.949,-6.362) K52(-8.864,-6.362) K53(-9.778,-6.362) K55(-10.692,-6.362) K56(-11.607,-6.362) K58(-12.521,-6.362) K60(-13.436,-6.362) K61(-14.35,-6.362) K63(-15.133,-6.054) K64(-15.783,-6.054) K65(-16.433,-6.054) K66(-17.084,-6.054) K67(-17.734,-6.054) K68(-18.352,-5.846) K70(-19.339,-5.744) L2(19.339,-5.814) L4(18.363,-5.814) L6(17.585,-5.34) L7(16.935,-5.34) L8(16.285,-5.34) L9(15.635,-5.34) L10(14.984,-5.34) L11(14.334,-5.34) L12(13.684,-5.34) L13(13.034,-5.34) L15(12.188,-5.038) L16(11.538,-5.038) L17(10.888,-5.038) L18(10.237,-5.038) L19(9.587,-5.038) L20(8.937,-5.038) L21(8.287,-5.038) L62(-14.644,-5.625) L63(-15.112,-5.168) L64(-15.763,-5.168) L65(-16.413,-5.168) L66(-17.063,-5.168) L67(-17.713,-5.168) L68(-18.364,-5.168) L69(-19.014,-5.168) L70(-19.664,-5.168) L71(-20.314,-5.168) M4(18.363,-5.151) M62(-14.644,-4.71) N3(18.689,-4.488) N6(17.585,-4.4) N7(16.935,-4.4) N8(16.285,-4.4) N9(15.635,-4.4) N10(14.984,-4.4) N11(14.334,-4.4) N12(13.684,-4.4) N13(13.034,-4.4) N15(12.188,-4.2) N16(11.538,-4.2) N17(10.888,-4.2) N18(10.237,-4.2) N19(9.587,-4.2) N20(8.937,-4.2) N21(8.287,-4.2) N63(-15.112,-4.253) N64(-15.763,-4.253) N65(-16.413,-4.253) N66(-17.063,-4.253) N67(-17.713,-4.253) N68(-18.364,-4.253) N69(-19.014,-4.253) N70(-19.664,-4.253) N71(-20.314,-4.253) P4(18.363,-3.825) P15(12.188,-3.362) P16(11.538,-3.362) P17(10.888,-3.362) P18(10.237,-3.362) P19(9.587,-3.362) P20(8.937,-3.362) P21(8.287,-3.362) P62(-14.644,-3.796) R6(17.585,-3.333) R7(16.935,-3.333) R8(16.285,-3.333) R9(15.635,-3.333) R10(14.984,-3.333) R11(14.334,-3.333) R12(13.684,-3.333) R13(13.034,-3.333) R63(-15.112,-3.339) R64(-15.763,-3.339) R65(-16.413,-3.339) R66(-17.063,-3.339) R67(-17.713,-3.339) R68(-18.364,-3.339) R69(-19.014,-3.339) R70(-19.664,-3.339) R71(-20.314,-3.339) T2(19.339,-3.162) T4(18.363,-3.162) T15(12.188,-2.523) T16(11.538,-2.523) T17(10.888,-2.523) T18(10.237,-2.523) T19(9.587,-2.523) T20(8.937,-2.523) T21(8.287,-2.523) T62(-14.644,-2.882) U4(18.363,-2.499) U6(17.585,-2.267) U7(16.935,-2.267) U8(16.285,-2.267) U9(15.635,-2.267) U10(14.984,-2.267) U11(14.334,-2.267) U12(13.684,-2.267) U13(13.034,-2.267) U63(-15.112,-2.424) U64(-15.763,-2.424) U65(-16.413,-2.424) U66(-17.063,-2.424) U67(-17.713,-2.424) U68(-18.364,-2.424) U69(-19.014,-2.424) U70(-19.664,-2.424) U71(-20.314,-2.424) V3(18.689,-1.836) V15(12.188,-1.685) V16(11.538,-1.685) V17(10.888,-1.685) V18(10.237,-1.685) V19(9.587,-1.685) V20(8.937,-1.685) V21(8.287,-1.685) V62(-14.644,-1.967) W4(18.363,-1.173) W6(17.585,-1.2) W7(16.935,-1.2) W8(16.285,-1.2) W9(15.635,-1.2) W10(14.984,-1.2) W11(14.334,-1.2) W12(13.684,-1.2) W13(13.034,-1.2) W63(-15.112,-1.51) W64(-15.763,-1.51) W65(-16.413,-1.51) W66(-17.063,-1.51) W67(-17.713,-1.51) W68(-18.364,-1.51) W69(-19.014,-1.51) W70(-19.664,-1.51) W71(-20.314,-1.51) Y15(12.188,-0.847) Y16(11.538,-0.847) Y17(10.888,-0.847) Y18(10.237,-0.847) Y19(9.587,-0.847) Y20(8.937,-0.847) Y21(8.287,-0.847) Y62(-14.644,-1.053)
  oval 0.254x0.343 smd: A6(17.467,-10.989) A7(16.791,-11.314) A9(15.664,-11.314) A10(14.989,-10.989) A11(14.313,-11.314) A13(13.186,-11.314) A14(12.511,-10.989) A15(11.835,-11.314) A17(10.708,-11.314) A18(10.033,-10.989) A19(9.357,-11.314) A21(8.23,-11.314) A22(7.555,-10.989) A23(6.879,-11.314) A25(5.752,-11.314) A26(5.077,-10.989) A27(4.401,-11.314) A29(3.274,-11.314) A30(2.599,-10.989) A31(1.923,-11.314) A33(0.796,-11.314) A34(0.121,-10.989) A36(-0.555,-11.314) A38(-1.682,-11.314) A39(-2.357,-10.989) A40(-3.033,-11.314) A42(-4.16,-11.314) A44(-4.835,-10.989) A45(-5.511,-11.314) A47(-6.638,-11.314) A48(-7.313,-10.989) A50(-7.989,-11.314) A52(-9.116,-11.314) A53(-9.791,-10.989) A54(-10.467,-11.314) A56(-11.594,-11.314) A58(-12.269,-10.989) A59(-12.945,-11.314) A61(-14.072,-11.314) A62(-14.747,-10.989) A63(-15.423,-11.314) A65(-16.55,-11.314) A66(-17.226,-10.989) A67(-17.901,-11.314) AY7(16.551,10.014) AY9(15.416,10.014) AY11(14.131,10.014) AY13(12.995,10.014) AY15(11.71,10.014) AY17(10.575,10.014) AY20(9.289,10.014) AY22(8.154,10.014) AY25(6.828,10.014) AY31(3.148,10.014) AY33(1.847,10.014) AY39(-1.833,10.014) AY42(-3.108,10.014) AY48(-6.789,10.014) AY50(-7.922,10.014) AY56(-11.602,10.014) AY59(-12.877,10.014) AY65(-16.558,10.014) AY67(-17.901,10.014) B7(16.791,-10.664) B9(15.664,-10.664) B11(14.313,-10.664) B13(13.186,-10.664) B15(11.835,-10.664) B17(10.708,-10.664) B19(9.357,-10.664) B21(8.23,-10.664) B23(6.879,-10.664) B25(5.752,-10.664) B27(4.401,-10.664) B29(3.274,-10.664) B31(1.923,-10.664) B33(0.796,-10.664) B36(-0.555,-10.664) B38(-1.682,-10.664) B40(-3.033,-10.664) B42(-4.16,-10.664) B45(-5.511,-10.664) B47(-6.638,-10.664) B50(-7.989,-10.664) B52(-9.116,-10.664) B54(-10.467,-10.664) B56(-11.594,-10.664) B59(-12.945,-10.664) B61(-14.072,-10.664) B63(-15.423,-10.664) B65(-16.55,-10.664) B67(-17.901,-10.664) BA4(18.366,10.689) BA6(17.173,10.258) BA7(16.61,10.664) BA9(15.416,10.664) BA10(14.753,10.258) BA11(14.189,10.664) BA13(12.995,10.664) BA14(12.332,10.258) BA15(11.768,10.664) BA17(10.575,10.664) BA18(9.912,10.258) BA20(9.348,10.664) BA22(8.154,10.664) BA25(6.828,10.664) BA26(6.165,10.339) BA27(5.502,10.664) BA29(4.473,10.664) BA30(3.811,10.339) BA31(3.148,10.664) BA33(1.847,10.664) BA34(1.184,10.339) BA35(0.521,10.664) BA37(-0.507,10.664) BA38(-1.17,10.339) BA39(-1.833,10.664) BA42(-3.108,10.664) BA43(-3.771,10.339) BA44(-4.434,10.664) BA46(-5.463,10.664) BA47(-6.126,10.339) BA48(-6.789,10.664) BA50(-7.922,10.664) BA51(-8.585,10.339) BA52(-9.248,10.664) BA54(-10.276,10.664) BA55(-10.939,10.339) BA56(-11.602,10.664) BA59(-12.877,10.664) BA60(-13.54,10.339) BA61(-14.203,10.664) BA63(-15.232,10.664) BA64(-15.895,10.339) BA65(-16.558,10.664) BA66(-17.221,10.339) BA67(-17.901,10.664) BB5(17.786,11.314) BB6(17.173,10.989) BB7(16.61,11.314) BB9(15.416,11.314) BB10(14.753,10.989) BB11(14.189,11.314) BB13(12.995,11.314) BB14(12.332,10.989) BB15(11.768,11.314) BB17(10.575,11.314) BB18(9.912,10.989) BB20(9.348,11.314) BB22(8.154,11.314) BB23(7.466,10.908) BB25(6.828,11.314) BB26(6.165,10.989) BB27(5.502,11.314) BB29(4.473,11.314) BB30(3.811,10.989) BB31(3.148,11.314) BB32(2.485,10.908) BB33(1.847,11.314) BB34(1.184,10.989) BB35(0.521,11.314) BB37(-0.507,11.314) BB38(-1.17,10.989) BB39(-1.833,11.314) BB41(-2.471,10.908) BB42(-3.108,11.314) BB43(-3.771,10.989) BB44(-4.434,11.314) BB46(-5.463,11.314) BB47(-6.126,10.989) BB48(-6.789,11.314) BB50(-7.922,11.314) BB51(-8.585,10.989) BB52(-9.248,11.314) BB54(-10.276,11.314) BB55(-10.939,10.989) BB56(-11.602,11.314) BB57(-12.24,10.908) BB59(-12.877,11.314) BB60(-13.54,10.989) BB61(-14.203,11.314) BB63(-15.232,11.314) BB64(-15.895,10.989) BB65(-16.558,11.314) BB66(-17.221,10.989) BB67(-17.901,11.314)
  oval 0.343x0.254 smd: AA1(19.989,-0.511) AB1(20.314,0.152) AB2(19.664,0.152) AB3(19.014,0.152) AC1(19.989,0.815) AC2(19.339,0.815) AD1(20.314,1.478) AD2(19.664,1.478) AD3(19.014,1.478) AF1(19.989,2.141) AF70(-19.664,1.84) AF71(-20.314,1.84) AG1(20.314,2.804) AG2(19.664,2.804) AG3(19.014,2.804) AG70(-19.339,2.503) AG71(-19.989,2.503) AH1(19.989,3.467) AH2(19.339,3.467) AH68(-18.364,3.166) AH69(-19.014,3.166) AH70(-19.664,3.166) AH71(-20.314,3.166) AJ1(20.314,4.13) AJ2(19.664,4.13) AJ3(19.014,4.13) AK70(-19.989,3.829) AL1(19.989,4.793) AL68(-18.364,4.492) AL69(-19.014,4.492) AL70(-19.664,4.492) AL71(-20.314,4.492) AM1(20.314,5.456) AM2(19.664,5.456) AM3(19.014,5.456) AM70(-19.339,5.155) AM71(-19.989,5.155) AN1(19.989,6.119) AN2(19.339,6.119) AN70(-19.664,5.818) AN71(-20.314,5.818) AP1(20.314,6.782) AP2(19.664,6.782) AP3(19.014,6.782) AR70(-19.664,6.846) AR71(-20.314,6.846) AT1(19.989,7.445) AT70(-19.339,7.509) AT71(-19.989,7.509) AU1(20.314,8.108) AU2(19.664,8.108) AU3(19.014,8.108) AU68(-18.364,8.147) AU69(-19.014,8.172) AU70(-19.664,8.172) AU71(-20.314,8.172) AV1(20.314,8.828) AV2(19.364,8.799) AV71(-20.314,8.901) AW2(19.689,9.362) AW3(19.039,9.362) E70(-19.664,-9.009) E71(-20.314,-8.901) F1(19.989,-8.466) F70(-19.212,-8.32) F71(-19.862,-8.384) G1(20.314,-7.803) G2(19.664,-7.803) G3(19.014,-7.803) G70(-19.664,-7.759) G71(-20.314,-7.759) H1(19.989,-7.14) H2(19.339,-7.14) H70(-19.339,-7.096) H71(-19.989,-7.096) J1(20.314,-6.477) J2(19.664,-6.477) J3(19.014,-6.477) J69(-19.014,-6.433) J70(-19.664,-6.433) J71(-20.314,-6.433) K71(-19.989,-5.744) L1(19.989,-5.814) M1(20.314,-5.151) M2(19.664,-5.151) M3(19.014,-5.151) N1(19.989,-4.488) N2(19.339,-4.488) P1(20.314,-3.825) P2(19.664,-3.825) P3(19.014,-3.825) T1(19.989,-3.162) U1(20.314,-2.499) U2(19.664,-2.499) U3(19.014,-2.499) V1(19.989,-1.836) V2(19.339,-1.836) W1(20.314,-1.173) W2(19.664,-1.173) W3(19.014,-1.173)
